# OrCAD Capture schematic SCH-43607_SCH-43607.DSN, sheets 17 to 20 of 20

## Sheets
17 P18_CPU MISC. &UART: size C
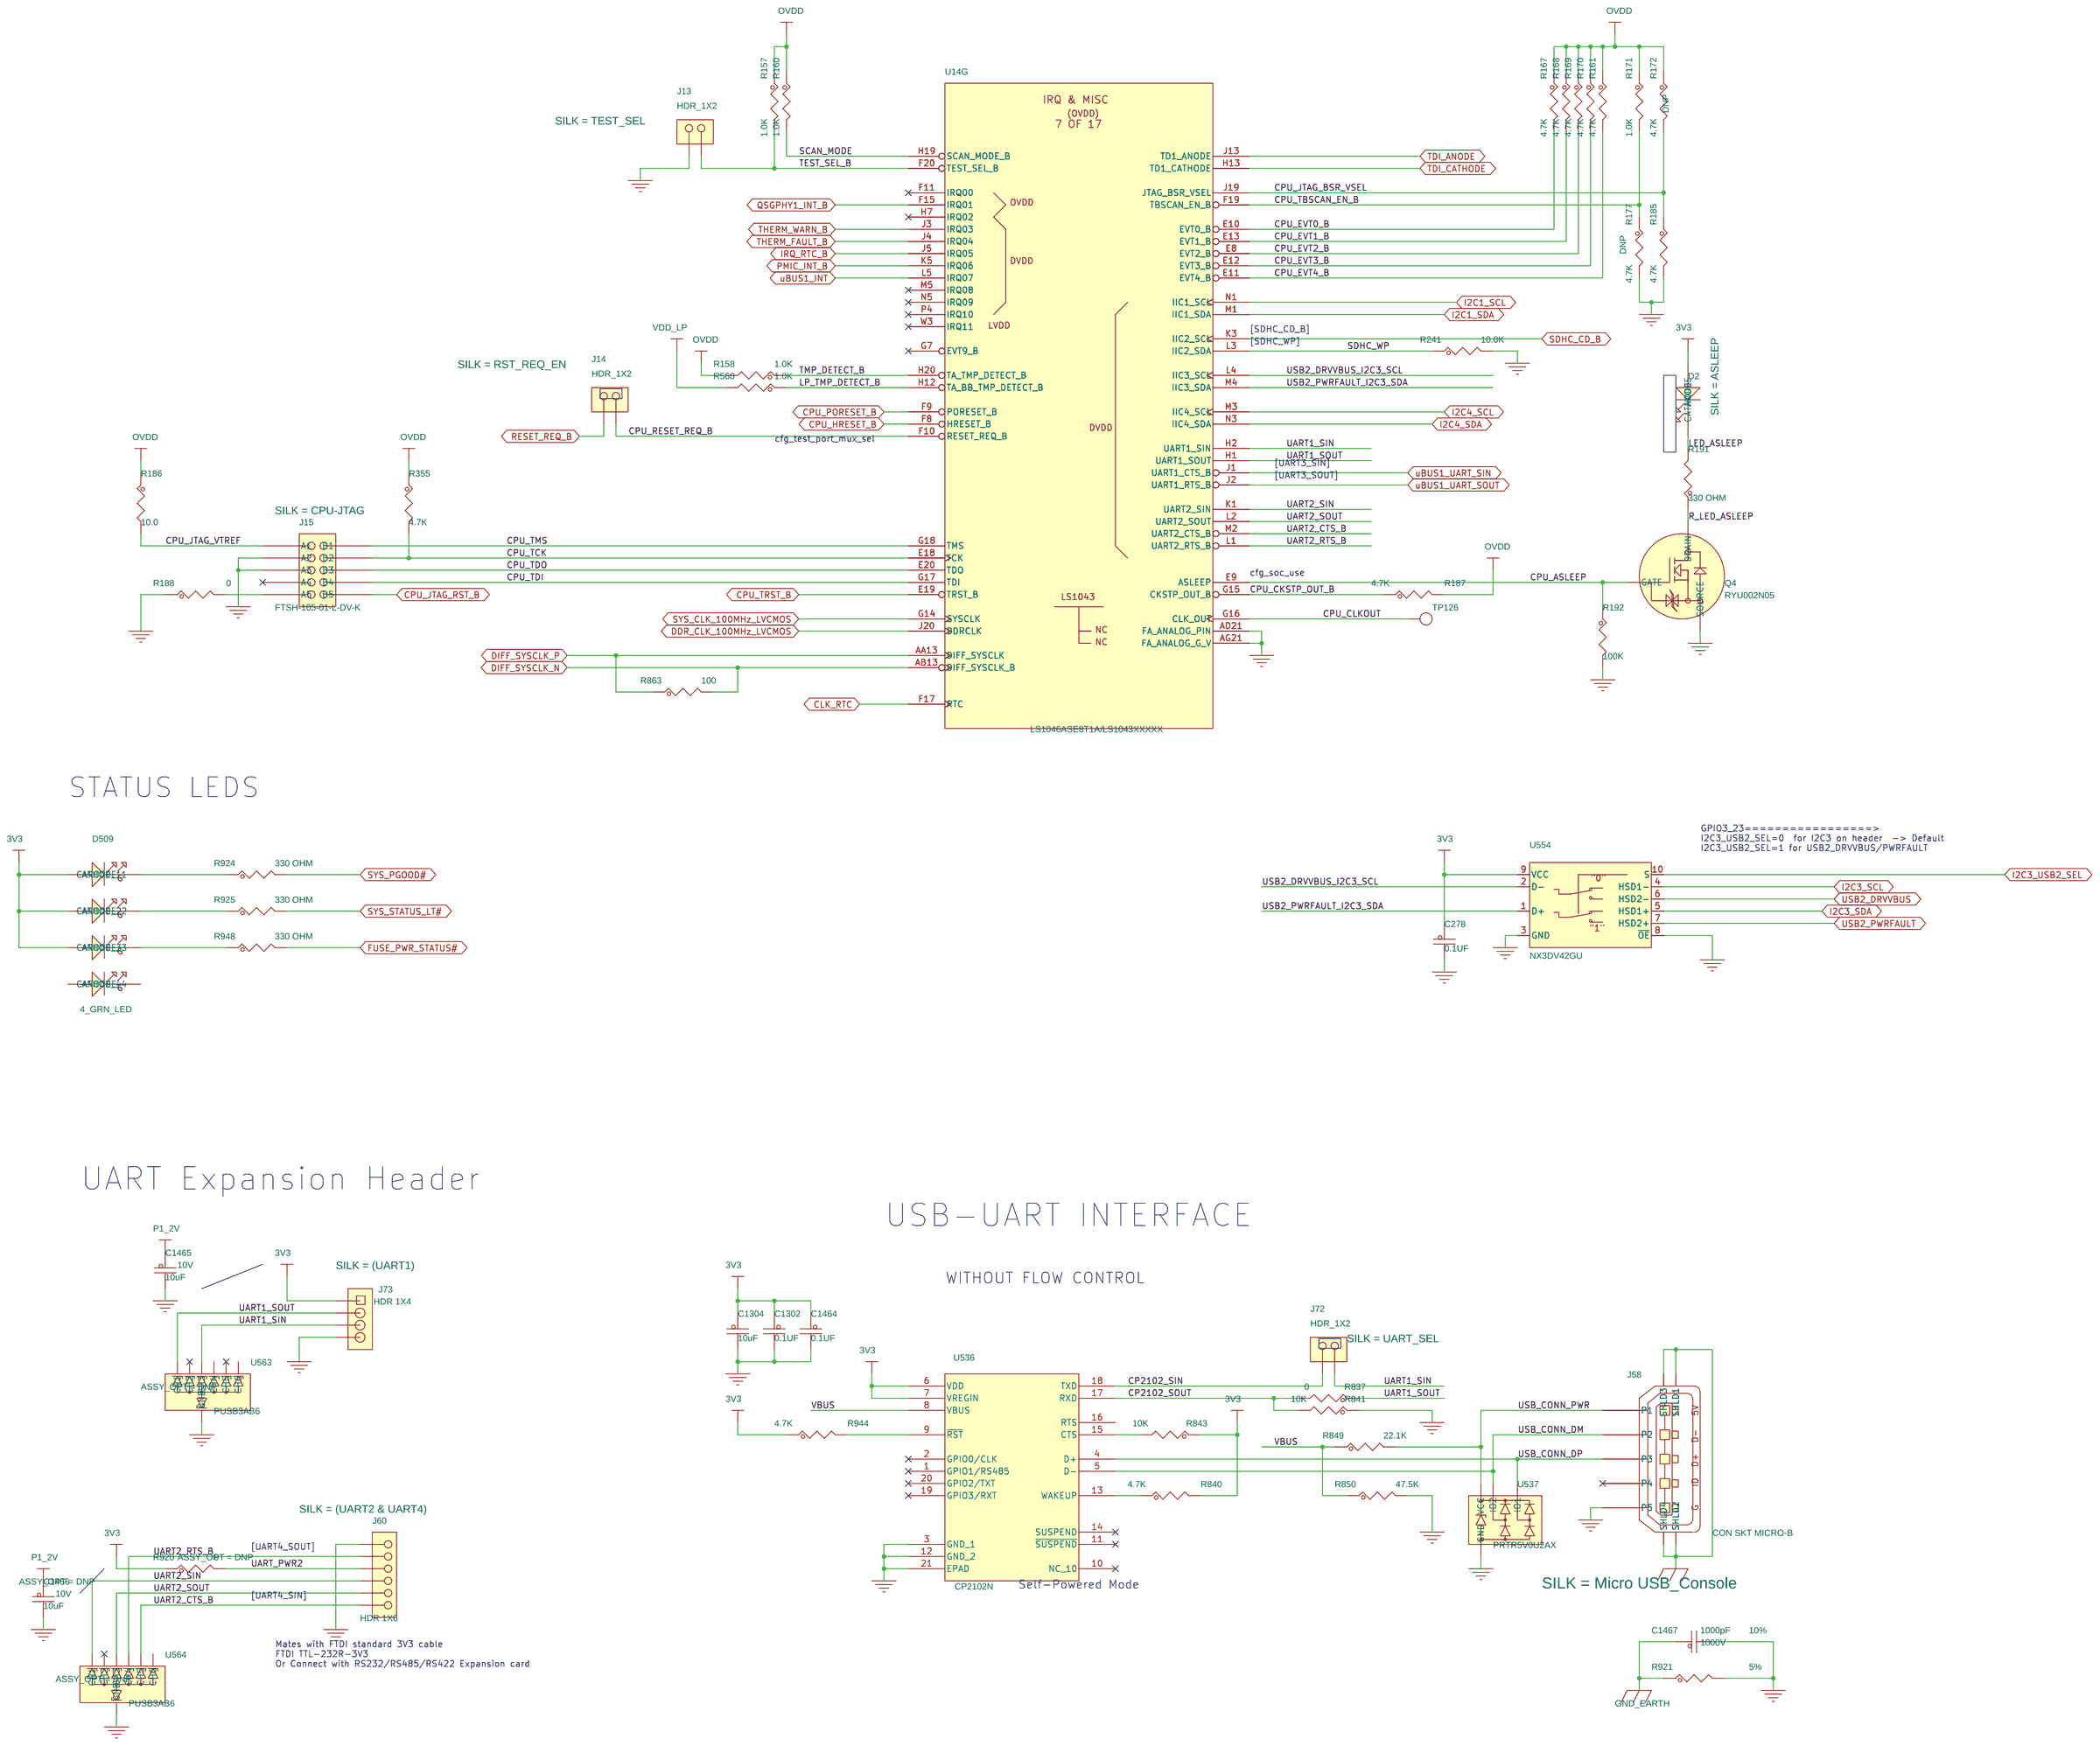
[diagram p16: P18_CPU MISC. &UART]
18 P19_CPU_RESET and GPIOs: size C
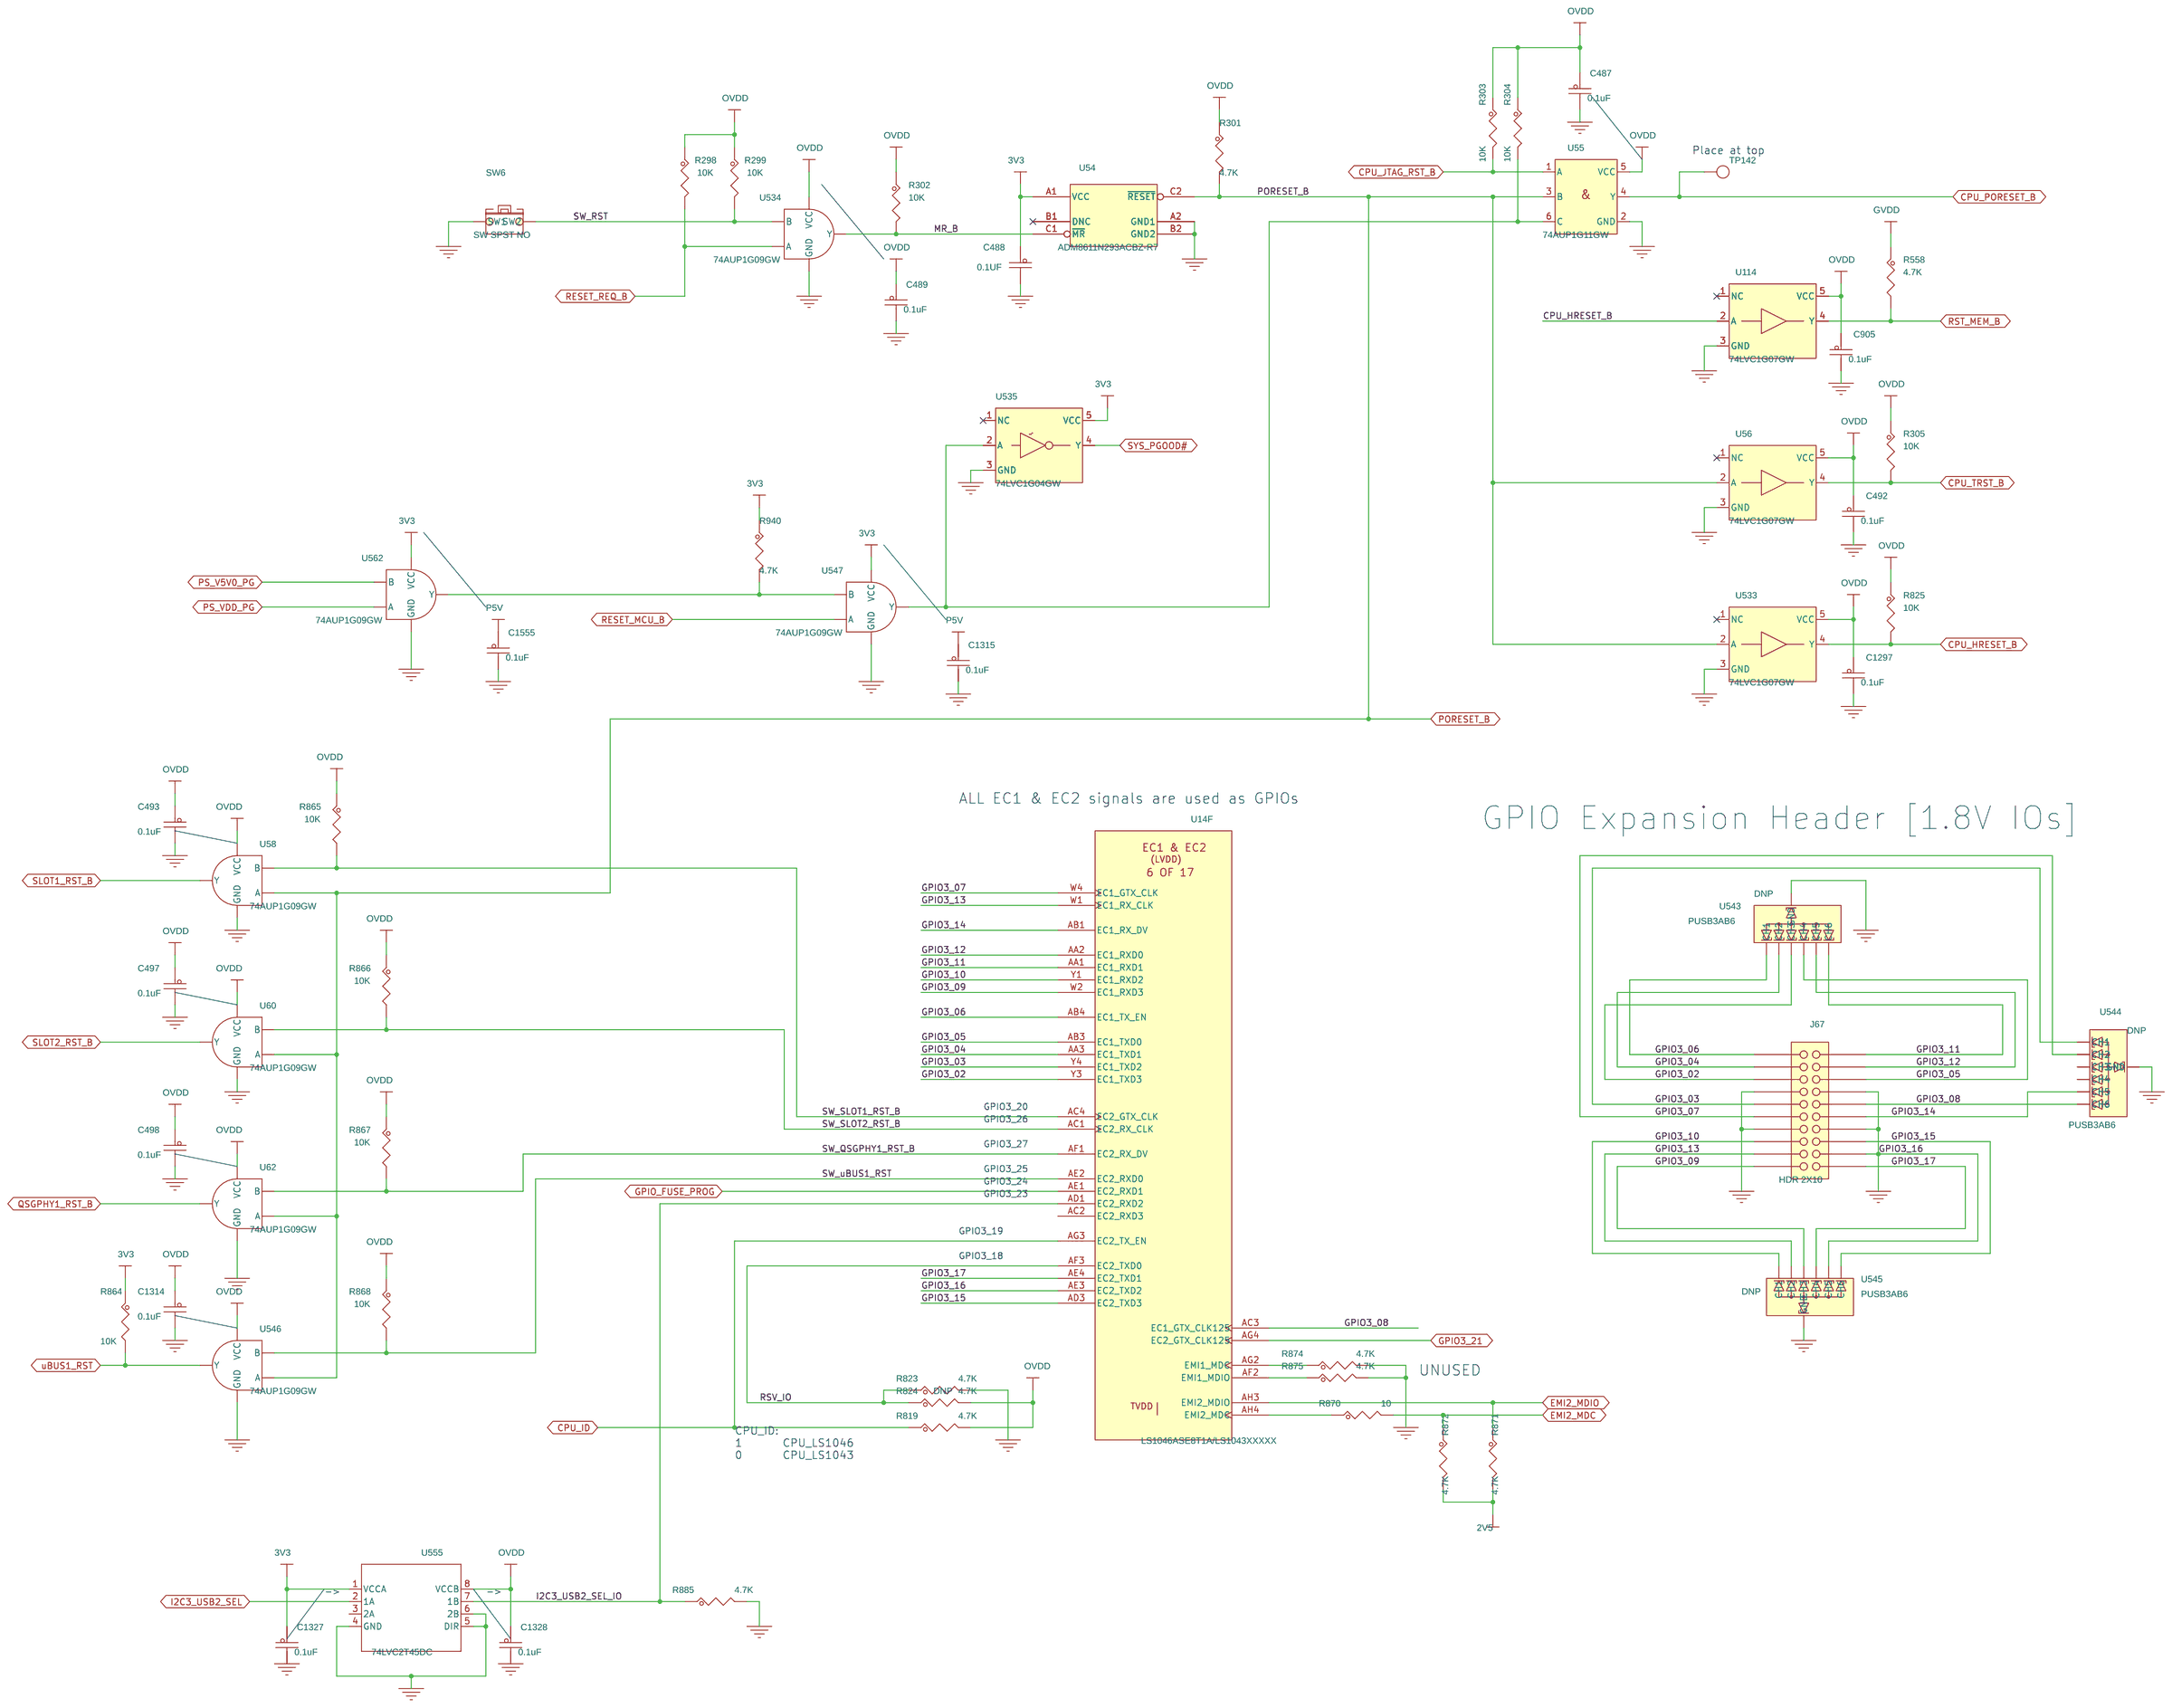
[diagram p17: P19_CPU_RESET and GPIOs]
19 P20_SD_SPI_MIKRO_CLICK: size C
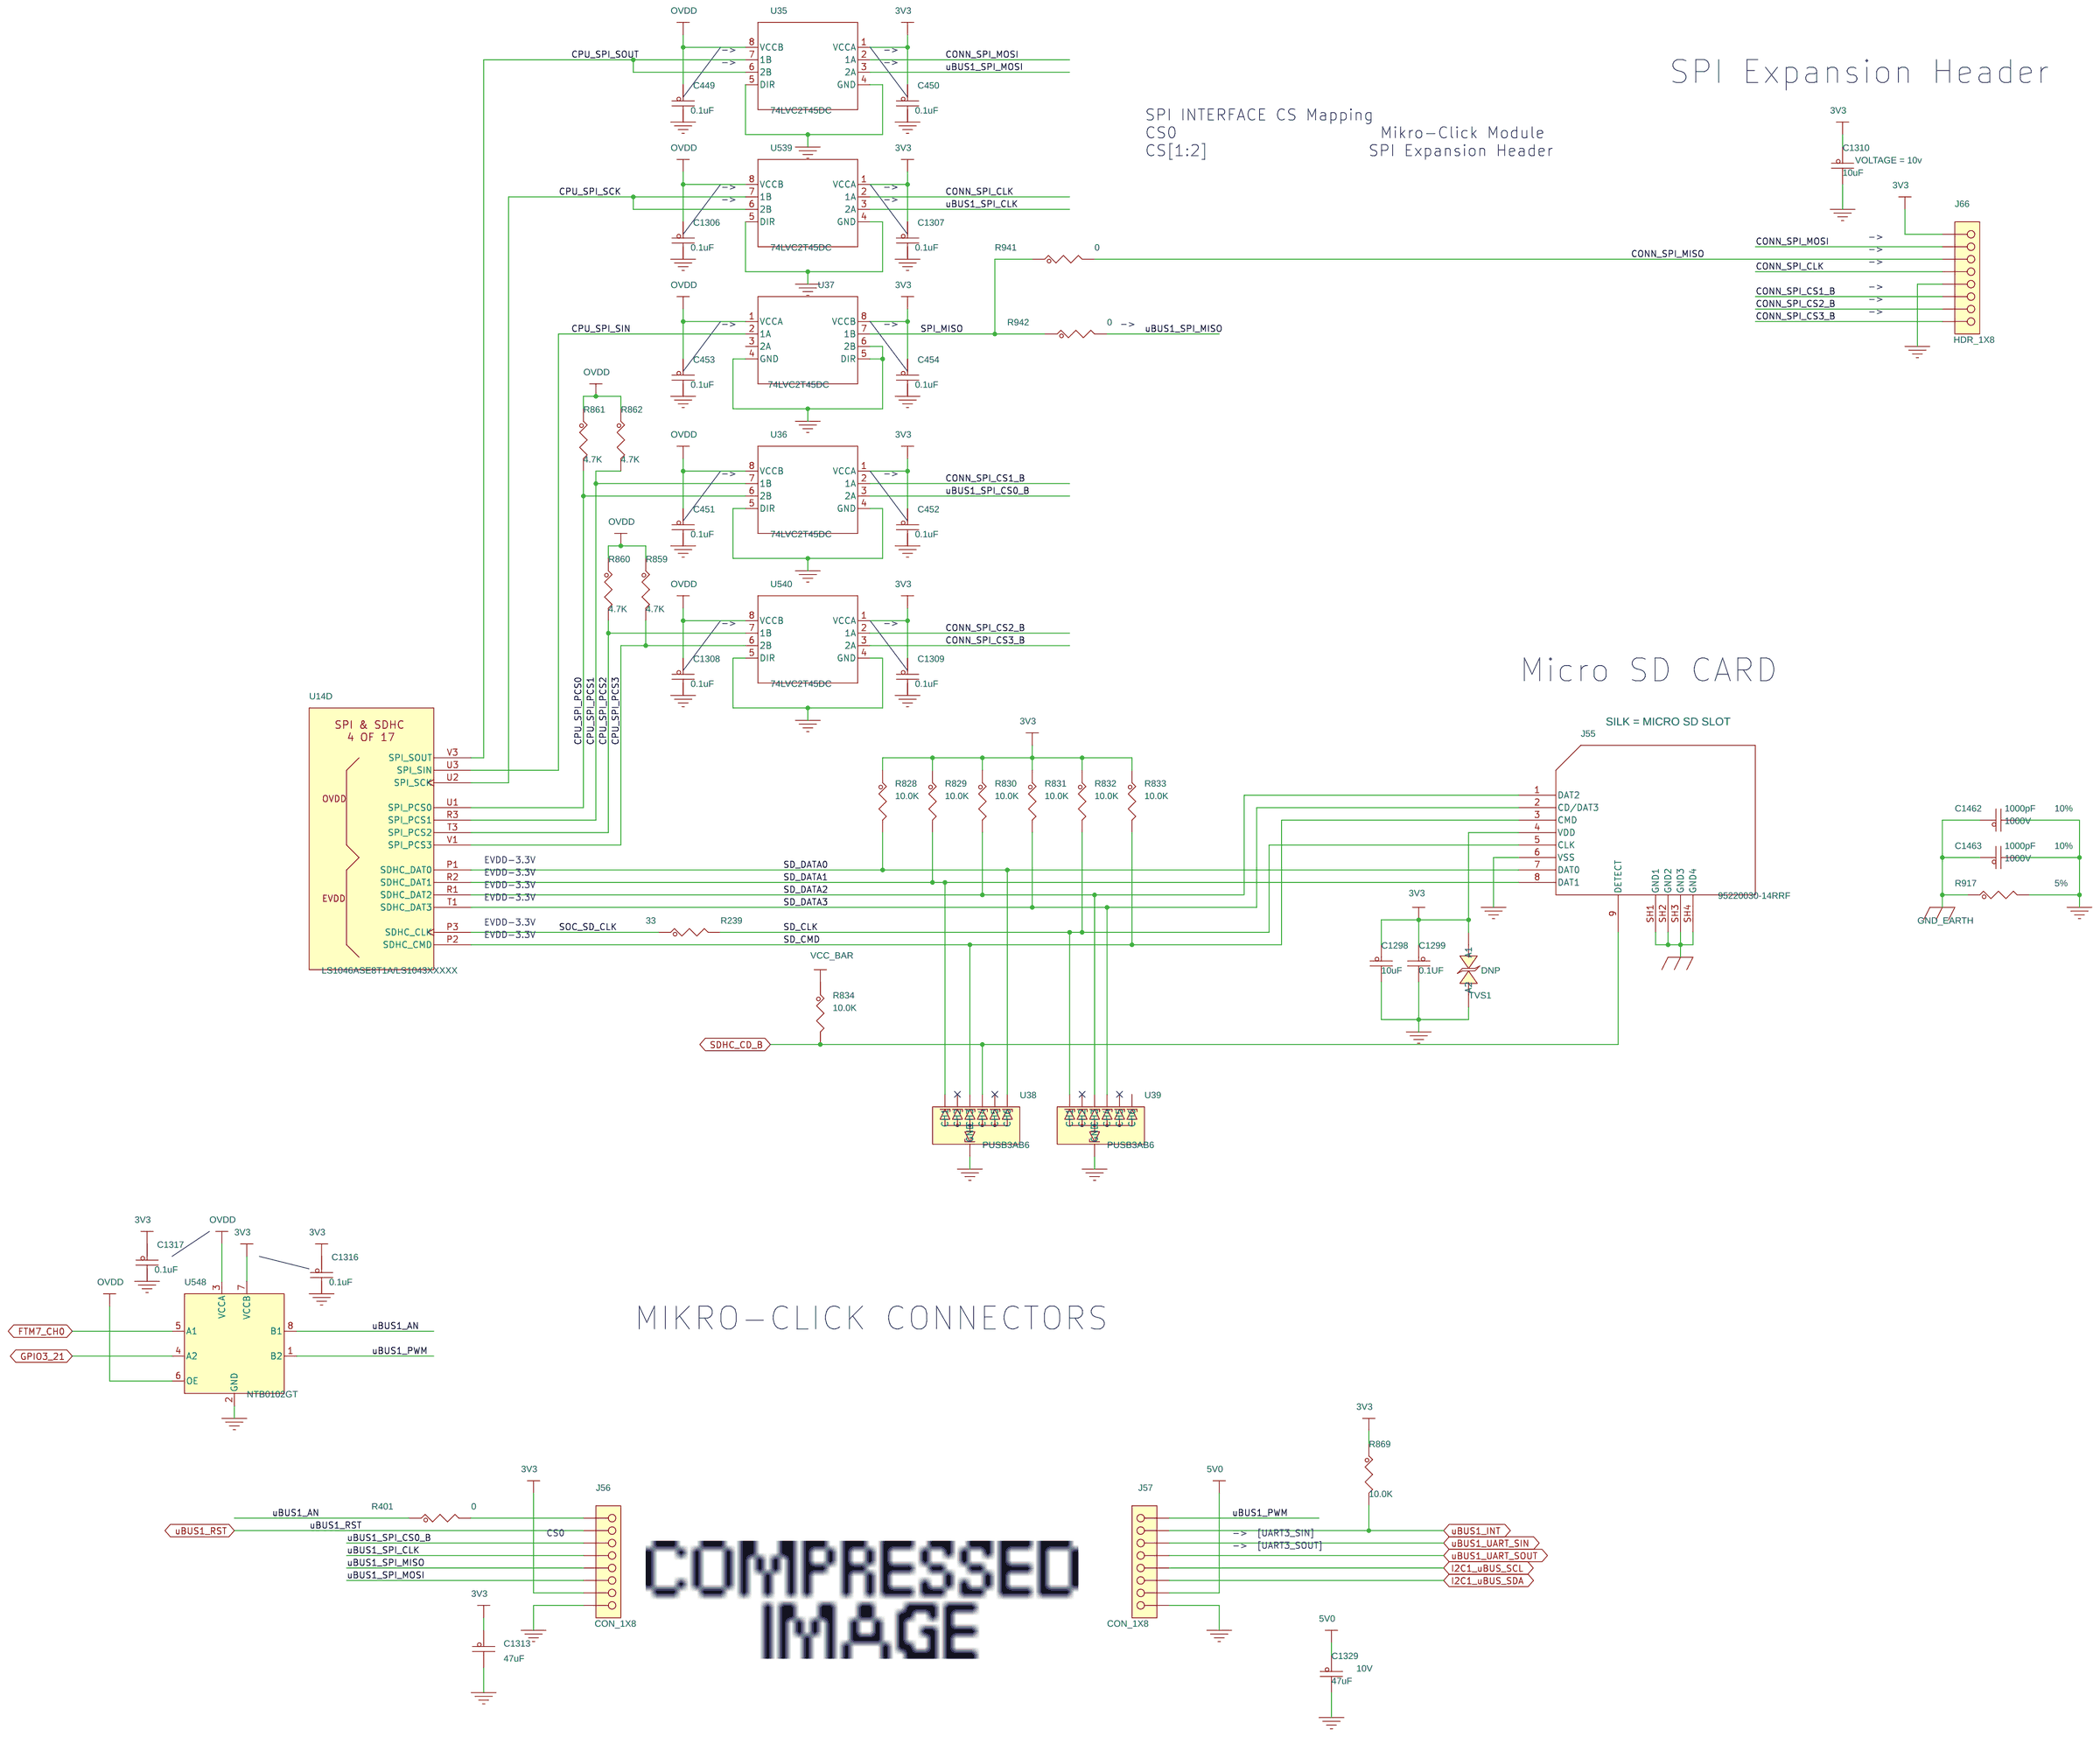
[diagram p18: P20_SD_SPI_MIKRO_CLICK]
20 P17_CPU USB[1:3]: size C
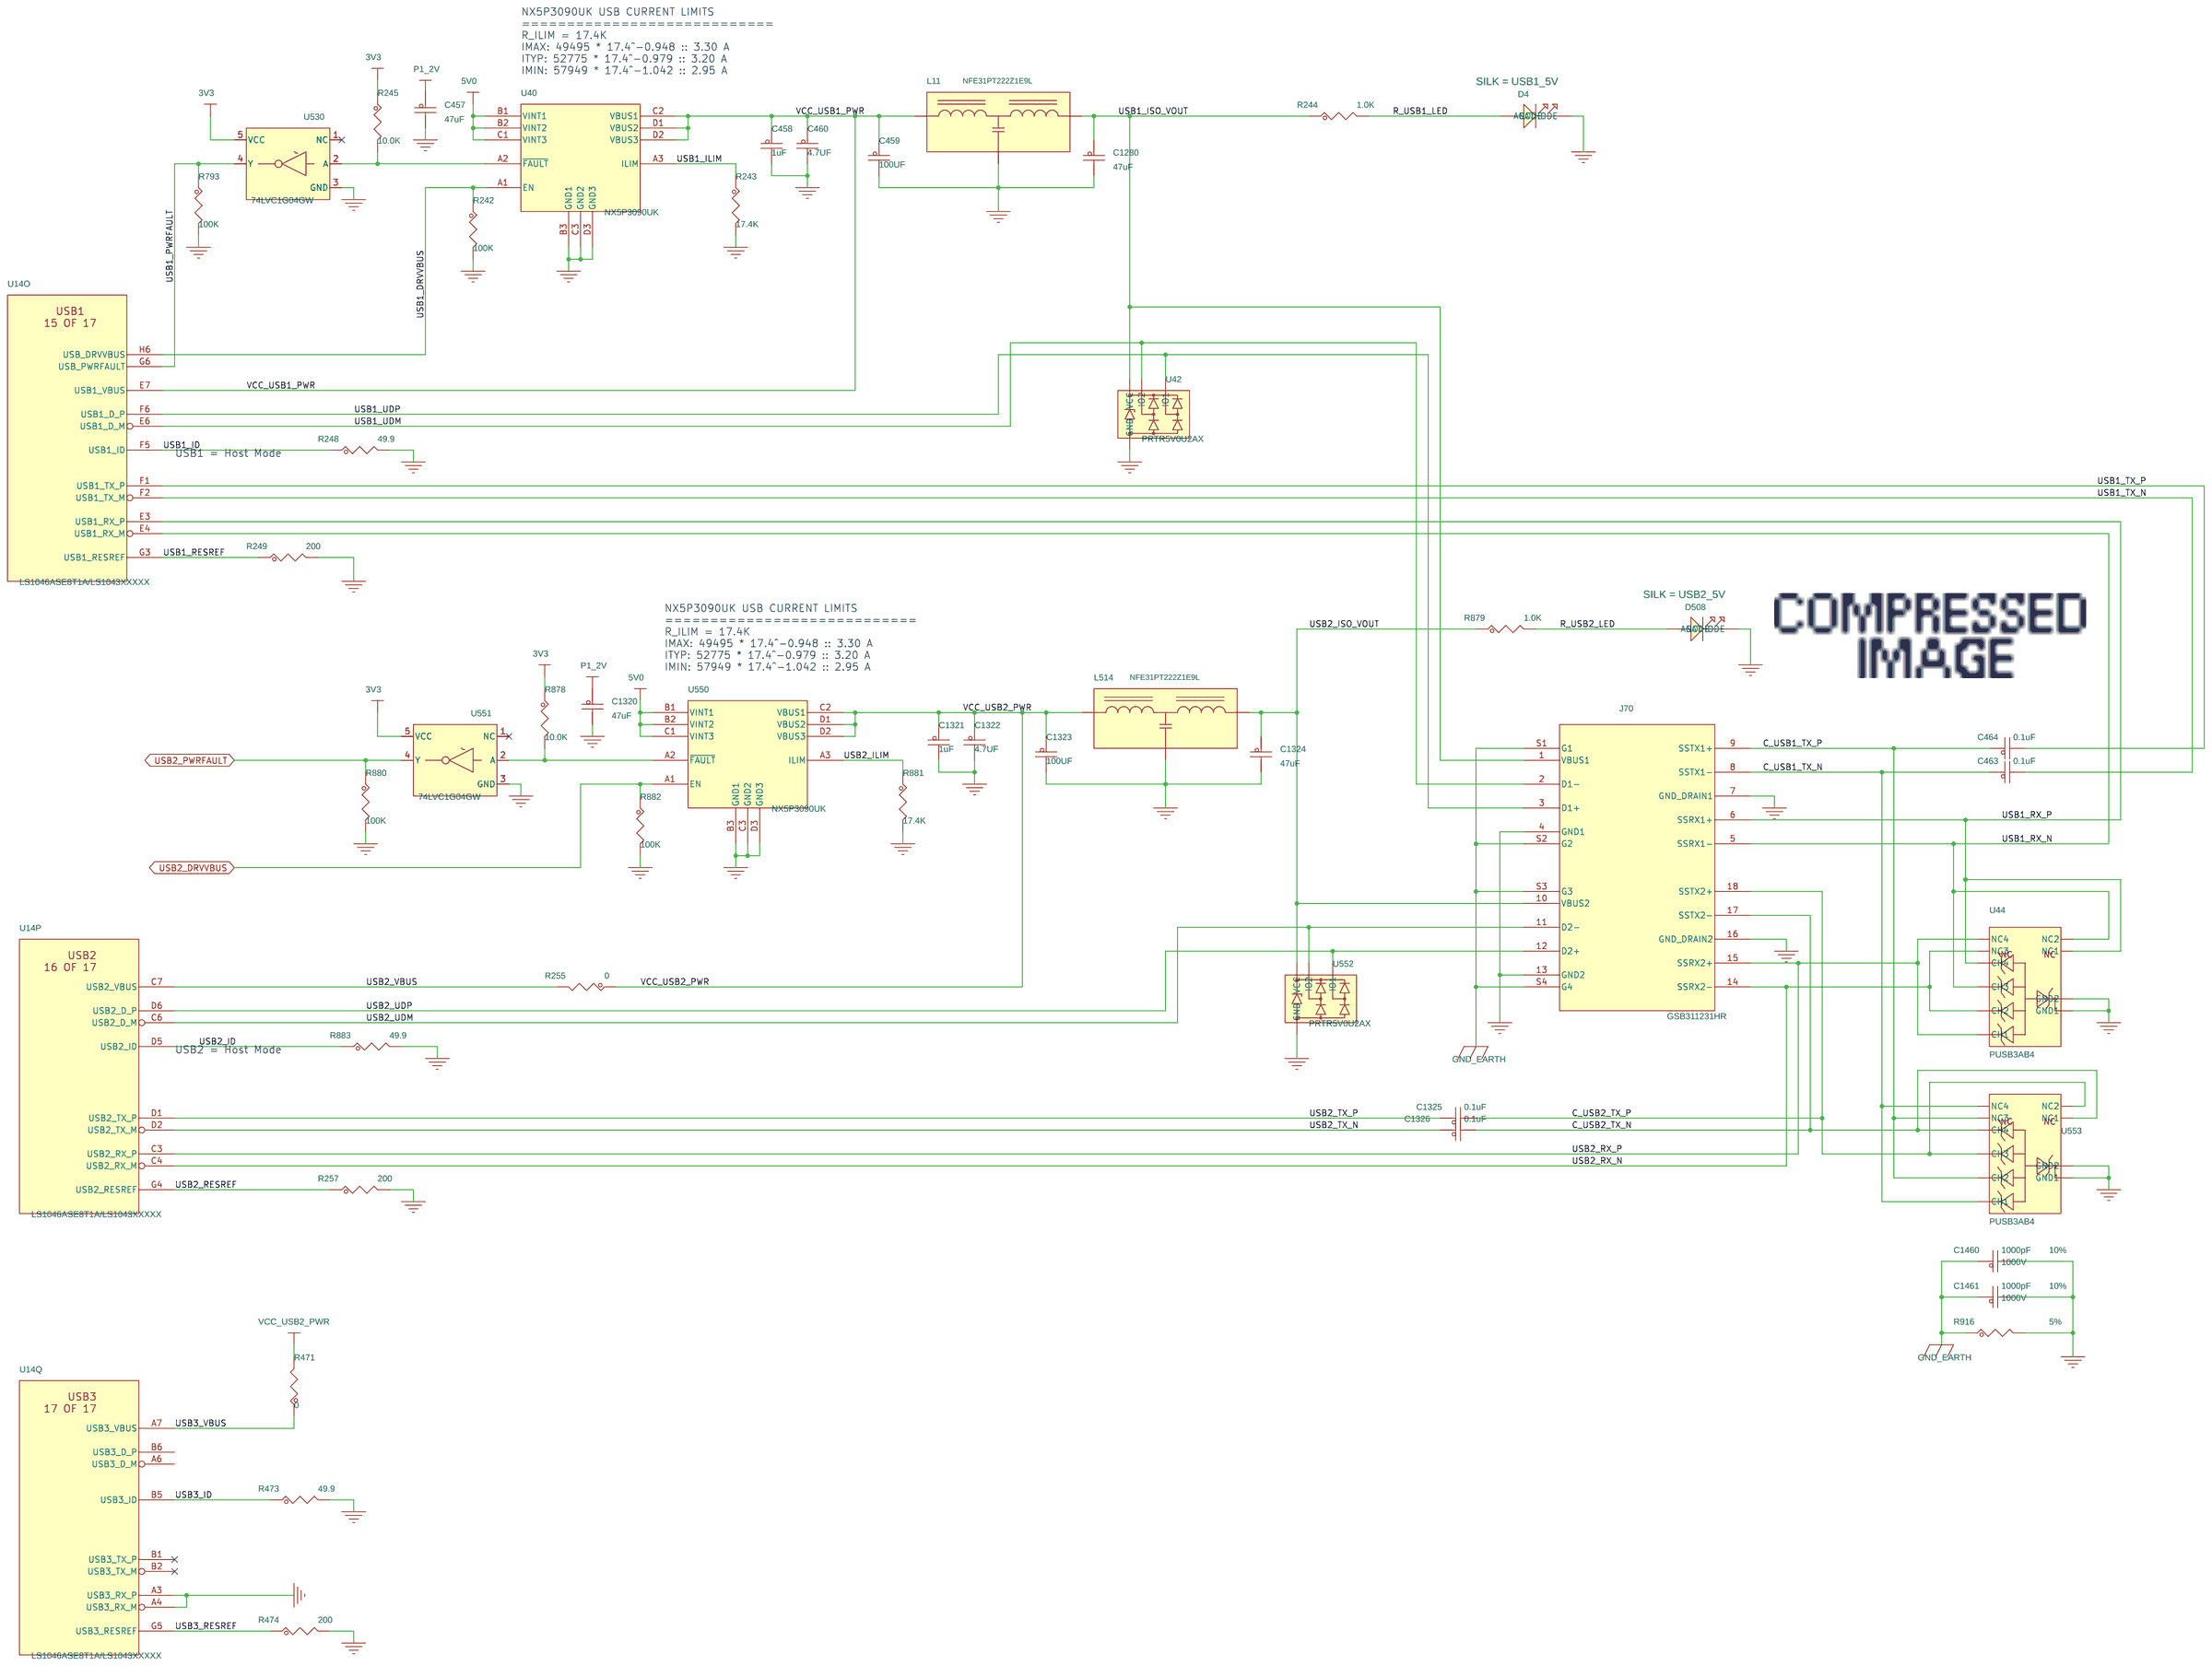
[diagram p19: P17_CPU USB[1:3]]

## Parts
sheet P17_CPU USB[1:3]
C457  47uF  [CC0805_OV]
C458  1uF  [CC0402_25]
C459  100UF  [CC1206_OV]
C460  4.7UF  [CC0402_25]
C463  0.1uF  [CC0201]
C464  0.1uF  [CC0201]
C1280  47uF  [CC0805_OV]
C1320  47uF  [CC0805_OV]
C1321  1uF  [CC0402_25]
C1322  4.7UF  [CC0402_25]
C1323  100UF  [CC1206_OV]
C1324  47uF  [CC0805_OV]
C1325  0.1uF  [CC0201]
C1326  0.1uF  [CC0201]
C1460  1000pF  [CC0805_OV]
C1461  1000pF  [CC0805_OV]
D4  LED_GREEN  [LED_0603]
D508  LED_GREEN  [LED_0603]
J70  GSB311231HR  [con_18p_usb3_ra_th]
L11  NFE31PT222Z1E9L  [IND_NFE31P]
L514  NFE31PT222Z1E9L  [IND_NFE31P]
R242  100K  [RC0402_25]
R243  17.4K  [RC0402_25]
R244  1.0K  [RC0402_25]
R245  10.0K  [RC0402_25]
R248  49.9  [RC0402_25]
R249  200  [RC0402_25]
R255  0  [RC0402_25]
R257  200  [RC0402_25]
R471  0  [RC0402_25]
R473  49.9  [RC0402_25]
R474  200  [RC0402_25]
R793  100K  [RC0402_25]
R878  10.0K  [RC0402_25]
R879  1.0K  [RC0402_25]
R880  100K  [RC0402_25]
R881  17.4K  [RC0402_25]
R882  100K  [RC0402_25]
R883  49.9  [RC0402_25]
R916  1.0M  [RC1206_OV]
U40  NX5P3090UK  [wlcsp12_0p4_1p38x1p68mm_smdp]
U42  PRTR5V0U2AX  [SOT143B]
U44  PUSB3AB4  [xson10_0p5_1p1x2p6mm]
U530  74LVC1G04GW  [sc70-5]
U550  NX5P3090UK  [wlcsp12_0p4_1p38x1p68mm_smdp]
U551  74LVC1G04GW  [sc70-5]
U552  PRTR5V0U2AX  [SOT143B]
U553  PUSB3AB4  [xson10_0p5_1p1x2p6mm]
sheet P18_CPU MISC. &UART
C278  0.1UF  [CC0402_25]
C1302  0.1UF  [CC0402_25]
C1304  10uF  [CC0603_OV]
C1464  0.1UF  [CC0402_25]
C1465  10uF  [CC0603_OV]
C1466  10uF  [CC0603_OV]
C1467  1000pF  [CC0805_OV]
D2  LED_YELLOW  [LED_0603]
D509  4_GRN_LED  [led_quad_2p54_th]
J13  HDR_1X2  [hdr1x2_50mil]
J14  HDR_1X2  [hdr1x2_50mil]
J15  FTSH-105-01-L-DV-K  [hdr205_10m_50_sm_k]
J58  CON SKT MICRO-B  [con_usb_5f_0p65_sm_ra_b]
J60  HDR 1X6  [hdr106_th_tsw]
J72  HDR_1X2  [hdr1x2_50mil]
J73  HDR 1X4  [JUMP1X4-6040]
Q4  RYU002N05  [SOT323_3]
R157  1.0K  [RC0402_25]
R158  1.0K  [RC0402_25]
R160  1.0K  [RC0402_25]
R161  4.7K  [RC0402_25]
R167  4.7K  [RC0402_25]
R168  4.7K  [RC0402_25]
R169  4.7K  [RC0402_25]
R170  4.7K  [RC0402_25]
R171  1.0K  [RC0402_25]
R172  4.7K  [RC0402_25]
R177  4.7K  [RC0402_25]
R185  4.7K  [RC0402_25]
R186  10.0  [RC0402_25]
R187  4.7K  [RC0402_25]
R188  0  [RC0402_25]
R191  330 OHM  [RC0402_25]
R192  100K  [RC0402_25]
R241  10.0K  [RC0402_25]
R355  4.7K  [RC0402_25]
R560  1.0K  [RC0402_25]
R837  0  [RC0402_25]
R840  4.7K  [RC0402_25]
R841  10K  [RC0402_25]
R843  10K  [RC0402_25]
R849  22.1K  [RC0402_25]
R850  47.5K  [RC0402_25]
R863  100  [RC0201]
R920  0  [RC0402_25]
R921  1.0M  [RC1206_OV]
R924  330 OHM  [RC0402_25]
R925  330 OHM  [RC0402_25]
R944  4.7K  [RC0402_25]
R948  330 OHM  [RC0402_25]
TP126  TPAD_020  [tpad_020]
U536  CP2102N  [qfn20_3x3mm_b]
U537  PRTR5V0U2AX  [SOT143B]
U554  NX3DV42GU  [uqfn10_0p4_1p45x1p85]
U563  PUSB3AB6  [xson7_0p5_2p2x1p2]
U564  PUSB3AB6  [xson7_0p5_2p2x1p2]
sheet P19_CPU_RESET and GPIOs
C487  0.1uF  [CC0201]
C488  0.1UF  [CC0402_25]
C489  0.1uF  [CC0201]
C492  0.1uF  [CC0201]
C493  0.1uF  [CC0201]
C497  0.1uF  [CC0201]
C498  0.1uF  [CC0201]
C905  0.1uF  [CC0201]
C1297  0.1uF  [CC0201]
C1314  0.1uF  [CC0201]
C1315  0.1uF  [CC0201]
C1327  0.1uF  [CC0201]
C1328  0.1uF  [CC0201]
C1555  0.1uF  [CC0201]
J67  HDR 2X10  [CON_TSM_20M_2P54_SM]
R298  10K  [RC0402_25]
R299  10K  [RC0402_25]
R301  4.7K  [RC0402_25]
R302  10K  [RC0402_25]
R303  10K  [RC0402_25]
R304  10K  [RC0402_25]
R305  10K  [RC0402_25]
R558  4.7K  [RC0402_25]
R819  4.7K  [RC0402_25]
R823  4.7K  [RC0402_25]
R824  4.7K  [RC0402_25]
R825  10K  [RC0402_25]
R864  10K  [RC0402_25]
R865  10K  [RC0402_25]
R866  10K  [RC0402_25]
R867  10K  [RC0402_25]
R868  10K  [RC0402_25]
R870  10  [RC0402_25]
R871  4.7K  [RC0402_25]
R872  4.7K  [RC0402_25]
R874  4.7K  [RC0402_25]
R875  4.7K  [RC0402_25]
R885  4.7K  [RC0402_25]
R940  4.7K  [RC0402_25]
SW6  SW SPST NO  [sw2_4p45_4x3_sm]
TP142  TPAD_020  [tpad_020]
U54  ADM8611N293ACBZ-R7  [wlcsp6_0p5_0p98x1p48]
U55  74AUP1G11GW  [sot-363_0p65_smt]
U56  74LVC1G07GW  [sc70-5]
U58  74AUP1G09GW  [SC70-5]
U60  74AUP1G09GW  [SC70-5]
U62  74AUP1G09GW  [SC70-5]
U114  74LVC1G07GW  [sc70-5]
U533  74LVC1G07GW  [sc70-5]
U534  74AUP1G09GW  [SC70-5]
U535  74LVC1G04GW  [sc70-5]
U543  PUSB3AB6  [xson7_0p5_2p2x1p2]
U544  PUSB3AB6  [xson7_0p5_2p2x1p2]
U545  PUSB3AB6  [xson7_0p5_2p2x1p2]
U546  74AUP1G09GW  [SC70-5]
U547  74AUP1G09GW  [SC70-5]
U555  74LVC2T45DC  [SSOP8_DCU]
U562  74AUP1G09GW  [SC70-5]
sheet P20_SD_SPI_MIKRO_CLICK
C449  0.1uF  [CC0201]
C450  0.1uF  [CC0201]
C451  0.1uF  [CC0201]
C452  0.1uF  [CC0201]
C453  0.1uF  [CC0201]
C454  0.1uF  [CC0201]
C1298  10uF  [CC0603_OV]
C1299  0.1UF  [CC0402_25]
C1306  0.1uF  [CC0201]
C1307  0.1uF  [CC0201]
C1308  0.1uF  [CC0201]
C1309  0.1uF  [CC0201]
C1310  10uF  [CC0603_OV]
C1313  47uF  [CC0805_OV]
C1316  0.1uF  [CC0201]
C1317  0.1uF  [CC0201]
C1329  47uF  [CC0805_OV]
C1462  1000pF  [CC0805_OV]
C1463  1000pF  [CC0805_OV]
J55  95220030-14RRF  [CON_SDCARD_95220]
J56  CON_1X8  [con_1x8_skt_2p54_th]
J57  CON_1X8  [con_1x8_skt_2p54_th]
J66  HDR_1X8  [JUMP1X8-6040]
R239  33  [RC0402_25]
R401  0  [RC0402_25]
R828  10.0K  [RC0402_25]
R829  10.0K  [RC0402_25]
R830  10.0K  [RC0402_25]
R831  10.0K  [RC0402_25]
R832  10.0K  [RC0402_25]
R833  10.0K  [RC0402_25]
R834  10.0K  [RC0402_25]
R859  4.7K  [RC0402_25]
R860  4.7K  [RC0402_25]
R861  4.7K  [RC0402_25]
R862  4.7K  [RC0402_25]
R869  10.0K  [RC0402_25]
R917  1.0M  [RC1206_OV]
R941  0  [RC0402_25]
R942  0  [RC0402_25]
TVS1  SESD0402X1BN  [diode_bidir_0402]
U14  LS1046ASE8T1A/LS1043XXXXX  [BGA780_0P8_23X23MM]  (sections A,B,C,D,E,F,G,H,I,J,K,L,M,N,O,P,Q)
U35  74LVC2T45DC  [SSOP8_DCU]
U36  74LVC2T45DC  [SSOP8_DCU]
U37  74LVC2T45DC  [SSOP8_DCU]
U38  PUSB3AB6  [xson7_0p5_2p2x1p2]
U39  PUSB3AB6  [xson7_0p5_2p2x1p2]
U539  74LVC2T45DC  [SSOP8_DCU]
U540  74LVC2T45DC  [SSOP8_DCU]
U548  NTB0102GT  [xson_8p]

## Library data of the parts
C457 C1280 C1313 C1320 C1324 C1329 = CAP_NP: CAP CER 47uF 10V 20% X5R 0805; AGILE_PN: 150-78979; CAD_APPROVED: Yes; FPLIST: CC0805_OV,CC0805,0805_CC; HEIGHT: 1.45 MM; MFG_NAME01: TDK; MFG_PN01: C2012X5R1A476M125AC; ROHS: Yes; Tolerance: 20%; VOLTAGE: 10V
C458 C1321 = CAP_NP: CAP CER 1uF 25V 10% X5R 0402; AGILE_PN: 150-80001; CAD_APPROVED: Yes; FPLIST: CC0402_25,CC0402_HD,0402_CC; HEIGHT: 0.55MM; MFG_NAME01: MURATA; MFG_PN01: GRM155R61E105KA12; PRIORITY_PN: 021-00242; ROHS: Yes; ROOM: USB2; Temp_Range: -55°C to +85°C; Tolerance: 10%; VOLTAGE: 25 V
C459 C1323 = CAP_NP: CAP CER 100UF 6.3V 20% X5R 1206; AGILE_PN: 150-77574; CAD_APPROVED: Yes; FPLIST: CC1206_OV,CC1206,1206_CC; HEIGHT: 1.9 MM; MFG_NAME01: Murata; MFG_PN01: GRM31CR60J107ME39L; ROHS: Yes; Tolerance: 20%; VOLTAGE: 6.3V
C460 C1322 = CAP_NP: CAP CER 4.7UF 10V 20% X5R 0402; AGILE_PN: 150-79667; CAD_APPROVED: Yes; FPLIST: CC0402_25,CC0402_HD,0402_CC; HEIGHT: 0.65MM; MFG_NAME01: Murata; MFG_PN01: GRM155R61A475MEAA; PRIORITY_PN: 921-00228; ROHS: Yes; ROOM: VTT_VREF_PS; Temp_Range: -55 to 85; Tolerance: 20%; VOLTAGE: 10V
C449-C454 C463 C464 C487 C489 C492 C493 C497 C498 C905 C1297 C1306-C1309 C1314-C1317 C1325-C1328 C1555 = CAP_NP: CAP CER 0.1uF 16V 10% X5R 0201; AGILE_PN: 150-80059; CAD_APPROVED: Yes; FPLIST: CC0201,CC0201_HD,0201_CC; HEIGHT: 0.33MM; MFG_NAME01: MURATA; MFG_PN01: GRM033R61C104KE14D; ROHS: Yes; Temp_Range: -55 to +85°C; Tolerance: 10%; VOLTAGE: 16V
C1460-C1463 C1467 = CAP_NP: CAP CER 1000pF 1000V 10% X7R 0805; AGILE_PN: 150-78841; CAD_APPROVED: Yes; FPLIST: CC0805_OV,CC0805,0805_CC; HEIGHT: 1.4MM; MFG_NAME01: Kemet; MFG_PN01: C0805C102KDRACTU; ROHS: Yes; Tolerance: 10%; VOLTAGE: 1000V
D4 = LED: LED ULTRA-BRIGHT GREEN SMT 0603; AGILE_PN: 370-75077; CAD_APPROVED: YES; HEIGHT: 0.8MM; MFG_NAME01: LITE ON; MFG_PN01: LTST-C190KGKT; ROHS: Yes; SILK: USB1_5V
D508 = LED: LED ULTRA-BRIGHT GREEN SMT 0603; AGILE_PN: 370-75077; CAD_APPROVED: YES; HEIGHT: 0.8MM; MFG_NAME01: LITE ON; MFG_PN01: LTST-C190KGKT; ROHS: Yes; SILK: USB2_5V
J70 = GSB311231HR_USB18P: CON 18 USB 3.0 SKT RA TH TYPE A 2MM SP 618H AU 94L; AGILE_PN: 210-80509; CAD_APPROVED: Yes; HEIGHT: 15.7MM; MFG_NAME01: Amphenol; ROHS: Yes
L11 L514 = NFE31P: FILTER LC 2200PF 6A 25V 1206; AGILE_PN: 180-75042; CAD_APPROVED: Yes; FPLIST: IND_NFE31P,NFM60R; HEIGHT: 1.75MM; MFG_NAME01: MURATA; PART_TYPE: FERRITE; ROHS: Yes; TOL: 50%; Tolerance: 50%
R192 R242 R793 R880 R882 = RES: RES MF 100K 1/16W 1% 0402; AGILE_PN: 470-76240; CAD_APPROVED: Yes; FPLIST: RC0402_25,RC0402_HD,0402_CC; HEIGHT: 0.4MM; MFG_NAME01: NIC COMPONENTS CORP; MFG_PN01: NRCL04F1003TRF; ROHS: Yes; Tolerance: 1%
R243 R881 = RES: RES MF 17.4K 1/10W 1% AEC-Q200 0402; AGILE_PN: 470-30972; CAD_APPROVED: Yes; FPLIST: RC0402_25,RC0402_HD,0402_CC; HEIGHT: 0.40 MM; MFG_NAME01: KOA SPEER; MFG_PN01: RK73H1ETTP1742F; ROHS: Yes; Temp_Range: -55C to +155C; Tolerance: 1%
R157 R158 R160 R171 R244 R560 R879 = RES: RES MF 1.0K 1/16W 1% 0402; AGILE_PN: 470-76037; CAD_APPROVED: Yes; FPLIST: RC0402_25,RC0402_HD,RC0402_X2,0402_CC; HEIGHT: 0.4MM; MFG_NAME01: YAGEO AMERICA; MFG_PN01: RC0402FR-071KL; ROHS: Yes; Tolerance: 1%
R241 R245 R828-R834 R869 R878 = RES: RES MF 10.0K 1/16W 1% 0402; AGILE_PN: 470-80574; CAD_APPROVED: Yes; FPLIST: RC0402_25,RC0402_HD,0402_CC; HEIGHT: 0.4MM; MFG_NAME01: WALSIN TECHNOLOGY CORP.; MFG_PN01: WR04X1002FTL; ROHS: Yes; Tolerance: 1%
R248 R473 R883 = RES: RES MF 49.9 OHM 1/16W 1% 0402; AGILE_PN: 470-75360; CAD_APPROVED: Yes; FPLIST: RC0402_25,RC0402_HD,0402_CC; HEIGHT: 0.4MM; MFG_NAME01: BOURNS; MFG_PN01: CR0402-FX-49R9GLF; ROHS: Yes; Tolerance: 1%
R249 R257 R474 = RES: RES MF 200 OHM 1/10W 1% 0402; AGILE_PN: 470-80287; CAD_APPROVED: Yes; FPLIST: RC0402_25,RC0402_HD,0402_CC; HEIGHT: 0.4 MM; MFG_NAME01: Panasonic; MFG_PN01: ERJ2RKF2000X; ROHS: Yes; Tolerance: 1%
R188 R255 R401 R471 R837 R941 R942 = RES: RES MF ZERO OHM 1/10W -- 0402; AGILE_PN: 470-79965; CAD_APPROVED: Yes; FPLIST: RC0402_25,RC0402_HD,RC0402_X2,0402_CC; HEIGHT: 0.4MM; MFG_NAME01: Panasonic; MFG_PN01: ERJ-2GE0R00X; ROHS: Yes
R916 R917 R921 = RES: RES MF 1.0M 1/4W 5% 1206; AGILE_PN: 470-75658; CAD_APPROVED: Yes; FPLIST: RC1206_OV,RC1206,1206_CC; HEIGHT: 0.75MM; MFG_NAME01: BOURNS; MFG_PN01: CR1206JW105ELF; ROHS: Yes; Tolerance: 5%
U40 U550 = NX5P3090UK_WLCSP12: IC USB PD TYPE C CURRENT LIMITED PWR SW 2.5-5.5V WLCSP12; AGILE_PN: 312-81574; CAD_APPROVED: Yes; HEIGHT: 0.565 MM; MFG_NAME01: NXP SEMICONDUCTORS; MFG_PN01: NX5P3090UK,012; ROHS: Yes
U42 U537 U552 = PRTR5V0U2AX: DIODE ARRAY ESD PROTECTION 5.5V AEC-Q101 SOT 143B; AGILE_PN: 480-78929; CAD_APPROVED: Yes; HEIGHT: 1.1MM; MFG_NAME01: NEXPERIA; MFG_PN01: PRTR5V0U2AX,215; ROHS: Yes; ROOM: USB1
U44 U553 = DIODE_ESD_4CH_PUSB3AB4: DIODE ARRAY ESD 3.3V 7A DFN2510A-10; AGILE_PN: 480-78994; CAD_APPROVED: Yes; HEIGHT: 0.5MM; MFG_NAME01: NEXPERIA; MFG_PN01: PUSB3AB4Z; ROHS: Yes
U530 U535 U551 = NC7SZ14: IC INV SGL 1.65-5.5V TSSOP5; AGILE_PN: 315-81077; CAD_APPROVED: Yes; HEIGHT: 1.1MM; MFG_NAME01: NEXPERIA; MFG_PN01: 74LVC1G04GW,125; ROHS: Yes
C278 = CAP_NP: CAP CER 0.1UF 25V 10% X5R 0402; AGILE_PN: 150-80045; CAD_APPROVED: Yes; FPLIST: CC0402_25,CC0402_HD,0402_CC; HEIGHT: 0.55MM; MFG_NAME01: Samsung Electro Mechanics; MFG_PN01: CL05A104KA5NNNC; PRIORITY_PN: 021-00389; ROHS: Yes; ROOM: LED; Tolerance: 10%; VOLTAGE: 25V
C488 C1299 C1302 C1464 = CAP_NP: CAP CER 0.1UF 25V 10% X5R 0402; AGILE_PN: 150-80045; CAD_APPROVED: Yes; FPLIST: CC0402_25,CC0402_HD,0402_CC; HEIGHT: 0.55MM; MFG_NAME01: Samsung Electro Mechanics; MFG_PN01: CL05A104KA5NNNC; ROHS: Yes; TOL: 10%; Tolerance: 10%; VOLTAGE: 25V
C1298 C1304 C1310 = CAP_NP: CAP CER 10UF 10V 10% X5R 0603; AGILE_PN: 150-78675; CAD_APPROVED: Yes; FPLIST: CC0603_OV,CC0603,0603_CC; HEIGHT: 1.016MM; MFG_NAME01: MURATA; MFG_PN01: GRM188R61A106KE69D; ROHS: Yes; Temp_Range: -55°C ~ 85°C; Tolerance: 10%; VOLTAGE: 10v
C1465 = CAP_NP: CAP CER 10UF 10V 10% X5R 0603; AGILE_PN: 150-78675; CAD_APPROVED: Yes; FPLIST: CC0603_OV,CC0603,0603_CC; HEIGHT: 1.016MM; MFG_NAME01: MURATA; MFG_PN01: GRM188R61A106KE69D; PRIORITY_PN: 021-00358; ROHS: Yes; ROOM: SDHC; SIGNAL_MODEL: DEFAULT_CAPACITOR_1e+07pF_2_1; TOL: 10%; Temp_Range: -55°C ~ 85°C; Tolerance: 10%; VOLTAGE: 10V
C1466 = CAP_NP: CAP CER 10UF 10V 10% X5R 0603; AGILE_PN: 150-78675; ASSY_OPT: DNP; CAD_APPROVED: Yes; FPLIST: CC0603_OV,CC0603,0603_CC; HEIGHT: 1.016MM; MFG_NAME01: MURATA; MFG_PN01: GRM188R61A106KE69D; PRIORITY_PN: 021-00358; ROHS: Yes; ROOM: SDHC; SIGNAL_MODEL: DEFAULT_CAPACITOR_1e+07pF_2_1; TOL: 10%; Temp_Range: -55°C ~ 85°C; Tolerance: 10%; VOLTAGE: 10V
D2 = LED: LED ULTRA-BRIGHT YELLOW 30MA 5V SMT 0603; AGILE_PN: 370-75076; CAD_APPROVED: Yes; HEIGHT: 0.8MM; MFG_NAME01: LITE ON; MFG_PN01: LTST-C190KSKT; ROHS: Yes; SILK: ASLEEP
D509 = LED_QUAD_GRN: LED GRN QUAD 25mA RA TH; AGILE_PN: 370-76782; CAD_APPROVED: Yes; HEIGHT: 12.25MM; MFG_NAME01: Kingbright; MFG_PN01: WP914CK/4GDT; ROHS: Yes; Temp_Range: -40 to +85C
J13 = CONN_HDR_2X1: HDR 1X2 TH 50MIL SP 165H AU 91L; AGILE_PN: 210-80212; CAD_APPROVED: Yes; HEIGHT: 4.2MM; MFG_NAME01: SULLINS ELECTRONICS CORP; MFG_PN01: GRPB021VWVN-RC; ROHS: Yes; SILK: TEST_SEL
J14 = CONN_HDR_2X1: HDR 1X2 TH 50MIL SP 165H AU 91L; AGILE_PN: 210-80212; CAD_APPROVED: Yes; HEIGHT: 4.2MM; MFG_NAME01: SULLINS ELECTRONICS CORP; MFG_PN01: GRPB021VWVN-RC; ROHS: Yes; SILK: RST_REQ_EN
J15 = CONN_HDR_5X2: HDR 2X5 SMT 50MIL CTR 246H AU; AGILE_PN: 211-79478; CAD_APPROVED: Yes; HEIGHT: 6.25MM; MFG_NAME01: SAMTEC; ROHS: Yes; SILK: CPU-JTAG
J58 = ZX62RD-AB-5P8_USB_MICROAB: CON 5 USB2.0 MICRO-B RA SMT 0.65MM; AGILE_PN: 211-80639; CAD_APPROVED: Yes; HEIGHT: 1.77MM; MFG_NAME01: MOLEX; MFG_PN01: 0476420001; ROHS: Yes; SILK: Micro USB_Console; Temp_Range: -30C to +85C
J60 = CONN_HDR_6X1: HDR 1X6 TH 100MIL SP 330H SN 100L; AGILE_PN: 210-80604; CAD_APPROVED: Yes; HEIGHT: 8.38MM; MFG_NAME01: SAMTEC; MFG_PN01: TSW-106-07-T-S; ROHS: Yes; SILK: (UART2 & UART4)
J72 = CONN_HDR_2X1: HDR 1X2 TH 50MIL SP 165H AU 91L; AGILE_PN: 210-80212; CAD_APPROVED: Yes; HEIGHT: 4.2MM; MFG_NAME01: SULLINS ELECTRONICS CORP; MFG_PN01: GRPB021VWVN-RC; ROHS: Yes; SILK: UART_SEL
J73 = HDR-1X4: HDR 1X4 TH 100MIL CTR  338H AU 100L; AGILE_PN: 210-81082; CAD_APPROVED: Yes; HEIGHT: 8.6MM; MFG_NAME01: SAMTEC; MFG_PN01: TSW-104-07-F-S; ROHS: Yes; SILK: (UART1)
Q4 = NMOSFET_3P_ESD_DIODE: TRAN NMOS SW 0.9V DRIVE 50V UMT3; AGILE_PN: 480-78966; CAD_APPROVED: Yes; HEIGHT: 0.9MM; MFG_NAME01: ROHM; ROHS: Yes
R161 R167-R170 R185 R187 R355 R819 R823 R840 R859-R862 R871 R872 R874 R875 R885 R944 = RES: RES MF 4.70K 1/16W 1% 0402; AGILE_PN: 470-75418; CAD_APPROVED: Yes; FPLIST: RC0402_25,RC0402_HD,0402_CC; HEIGHT: 0.4mm; MFG_NAME01: WALSIN TECHNOLOGY CORP.; MFG_PN01: WR04X4701FTL; ROHS: Yes; Tolerance: 1%
R172 R177 R824 = RES: RES MF 4.70K 1/16W 1% 0402; AGILE_PN: 470-75418; ASSY_OPT: DNP; CAD_APPROVED: Yes; FPLIST: RC0402_25,RC0402_HD,0402_CC; HEIGHT: 0.4mm; MFG_NAME01: WALSIN TECHNOLOGY CORP.; MFG_PN01: WR04X4701FTL; ROHS: Yes; Tolerance: 1%
R186 = RES: RES MF 10.0 OHM 1/16W 1% 0402; AGILE_PN: 470-76090; CAD_APPROVED: Yes; FPLIST: RC0402_25,RC0402_HD,0402_CC; HEIGHT: 0.4MM; MFG_NAME01: BOURNS; MFG_PN01: CR0402-FX-10R0GLF; ROHS: Yes; Tolerance: 1%
R191 R924 R925 R948 = RES: RES MF 330 OHM 1/16W 1% 0402; AGILE_PN: 470-80566; CAD_APPROVED: Yes; FPLIST: RC0402_25,RC0402_HD,0402_CC; HEIGHT: 0.4MM; MFG_NAME01: WALSIN TECHNOLOGY CORP.; MFG_PN01: WR04X3300FTL; ROHS: Yes; Tolerance: 1%
R298 R299 R302-R305 R825 R841 R843 R864-R868 = RES: RES MF 10K 1/5W 1% AEC-Q200 0402; AGILE_PN: 470-80881; CAD_APPROVED: Yes; FPLIST: RC0402_25,RC0402_HD,0402_CC; HEIGHT: 0.4MM; MFG_NAME01: VISHAY INTERTECHNOLOGY; MFG_PN01: CRCW040210K0FKEDHP; ROHS: Yes; Temp_Range: -55&#8451; to 155&#8451;; Tolerance: 1%
R849 = RES: RES MF 22.1K 1/10W 1% AEC-Q200 0402; AGILE_PN: 470-30984; CAD_APPROVED: Yes; FPLIST: RC0402_25,RC0402_HD,0402_CC; HEIGHT: 0.40 MM; MFG_NAME01: KOA SPEER; MFG_PN01: RK73H1ETTP2212F; ROHS: Yes; Temp_Range: -55C to +155C; Tolerance: 1%
R850 = RES: RES MF 47.5K 1/16W 1% 0402; AGILE_PN: 470-80836; CAD_APPROVED: Yes; FPLIST: RC0402_25,RC0402_HD,0402_CC; HEIGHT: 0.4MM; MFG_NAME01: WALSIN TECHNOLOGY CORP.; MFG_PN01: WR04X4752FTL; ROHS: Yes; Temp_Range: -55°C ~ 155°C; Tolerance: 1%
R863 = RES: RES MF 100 OHM 1/20W 1% AEC-Q200 0201; AGILE_PN: 470-81361; CAD_APPROVED: Yes; FPLIST: RC0201,0201_CC; HEIGHT: 0.26 MM; MFG_NAME01: YAGEO AMERICA; MFG_PN01: AC0201FR-07100RL; ROHS: Yes; Temp_Range: -55&#8451; to 155&#8451;
R920 = RES: RES MF ZERO OHM 1/10W -- 0402; AGILE_PN: 470-79965; ASSY_OPT: DNP; CAD_APPROVED: Yes; FPLIST: RC0402_25,RC0402_HD,RC0402_X2,0402_CC; HEIGHT: 0.4MM; MFG_NAME01: Panasonic; MFG_PN01: ERJ-2GE0R00X; ROHS: Yes
TP126 TP142 = TestLoop: TEST POINT PAD 0.5MM DIA SMT, NO PART TO ORDER; AGILE_PN: 211-77484; CAD_APPROVED: Yes; HEIGHT: 0.1MM; ROHS: Yes
U536 = CP2102N_QFN20: IC USB-TO-UART BRIDGE 3-3.6V QFN20; AGILE_PN: 312-82164; CAD_APPROVED: Yes; HEIGHT: 0.8MM; MFG_NAME01: SILICON LABORATORIES; MFG_PN01: CP2102N-A01-GQFN20; ROHS: Yes; Temp_Range: -40 to +85C
U554 = NX3DV42GU_XQFN_10P_A: IC LIN SW DPDT DUAL USB 2.0 3-4.3V XQFN10; AGILE_PN: 312-81289; CAD_APPROVED: Yes; HEIGHT: 0.5MM; MFG_NAME01: NXP SEMICONDUCTORS; MFG_PN01: NX3DV42GU,115; ROHS: Yes
U543-U545 U563 U564 = PUSB3AB6: DIODE ARRAY ESD PROTECTION 15 kV 3.3V XSON7; AGILE_PN: 480-78930; ASSY_OPT: DNP; CAD_APPROVED: Yes; HEIGHT: 0.5MM; MFG_NAME01: NEXPERIA; MFG_PN01: PUSB3AB6Z; ROHS: Yes
J67 = CONN_HDR_10X2: HDR 2X10 SMT 100MIL CTR 380H AU; AGILE_PN: 211-30042; CAD_APPROVED: Yes; HEIGHT: 9.85mm; MFG_NAME01: SAMTEC; MFG_PN01: TSM-110-01-L-DV-M-TR; ROHS: Yes
R301 R558 R940 = RES: RES MF 4.7K 1/10W 1% AEC-Q200 0402; AGILE_PN: 470-81976; CAD_APPROVED: Yes; FPLIST: RC0402_25,RC0402_HD,0402_CC; HEIGHT: 0.4MM; MFG_NAME01: KOA SPEER; MFG_PN01: RK73H1ETTP4701F; ROHS: Yes; Temp_Range: -55C to +155C; Tolerance: 1%
R870 = RES: RES MF 10 OHM 1/16W 1% AEC-Q200 0402; AGILE_PN: 470-80978; CAD_APPROVED: Yes; FPLIST: RC0402_25,RC0402_HD,0402_CC; HEIGHT: 0.4MM; MFG_NAME01: KOA SPEER; MFG_PN01: RK73H1ETTP10R0F; ROHS: Yes; Tolerance: 1%
SW6 = SW2P_SPST: SW SPST MOM NO TACT 20MA 12V SMT; AGILE_PN: 510-78069; CAD_APPROVED: Yes; HEIGHT: 2.3MM; MFG_NAME01: Fodot Electronics Co.,Ltd.; MFG_PN01: T044S-N020FRT30B; ROHS: Yes
U54 = ADM8611_WLCSP_6P: IC SUPERVISORY ULTRALOW PWR 0.9-5.5V WLCSP6; AGILE_PN: 315-81882; CAD_APPROVED: Yes; HEIGHT: 0.66MM; MFG_NAME01: ANALOG DEVICES; ROHS: Yes; Temp_Range: -40C to +85C
U55 = 74AUP1G11GW: IC GATE AND 3INPUT 0.8-3.6V SOT363; AGILE_PN: 312-81800; CAD_APPROVED: Yes; HEIGHT: 1.1MM; MFG_NAME01: NEXPERIA; MFG_PN01: 74AUP1G11GW,125; ROHS: Yes; Temp_Range: -40C to +125C
U56 U114 U533 = 74AUP1G07GW: IC BUF NON-INV SGL 1.65-5.5V TSSOP5; AGILE_PN: 312-81328; CAD_APPROVED: Yes; HEIGHT: 1.1 MM; MFG_NAME01: NEXPERIA; MFG_PN01: 74LVC1G07GW,125; ROHS: Yes
U58 U60 U62 U534 U546 U547 U562 = GATE_AND_SGL: IC GATE AND 2 INPUT OPEN DRAIN OUTPUT 0.8-3.6V TSSOP5; AGILE_PN: 312-80643; CAD_APPROVED: Yes; HEIGHT: 1.1 MM; MFG_NAME01: NEXPERIA; MFG_PN01: 74AUP1G09GW,125; ROHS: Yes
U35-U37 U539 U540 U555 = 74LVC2T45DC_8P: IC TRANSLATING XCVR DUAL BIT/SUPPLY TS 1.2-5.5V VSSOP8; AGILE_PN: 312-81751; CAD_APPROVED: Yes; HEIGHT: 1MM; MFG_NAME01: NEXPERIA; ROHS: Yes; Temp_Range: -40°C to +125°C
J55 = CON8_SDCARD_DETECT: CON 8 SKT SD/MMC RA SMT 43MIL SP 84H AU; AGILE_PN: 211-80169; CAD_APPROVED: Yes; HEIGHT: 2.13MM; MFG_NAME01: ANYTRONIC CORPORATION LIMITED; ROHS: Yes; SILK: MICRO SD SLOT; Temp_Range: -25C to +85C
J56 J57 = CONN_HDR_8X1: CON 1X8 SKT TH 100MIL SP 344H AU 394L; AGILE_PN: 210-81601; CAD_APPROVED: Yes; HEIGHT: 8.75MM; MFG_NAME01: ANYTRONIC CORPORATION LIMITED; MFG_PN01: 08001S3 0811-100-29LF; ROHS: Yes; Temp_Range: -40°C to +105°C
J66 = CONN_HDR_8X1: HDR 1X8 TH 100MIL SP 330H AU 100L; AGILE_PN: 210-75691; CAD_APPROVED: Yes; HEIGHT: 8.382 MM; MFG_NAME01: SAMTEC; MFG_PN01: TSW-108-07-G-S; ROHS: Yes
R239 = RES: RES MF 33 OHM 1/16W 5% 0402; AGILE_PN: 470-75634; CAD_APPROVED: Yes; FPLIST: RC0402_25,RC0402_HD,0402_CC; HEIGHT: 0.41mm; MFG_NAME01: SMEC; MFG_PN01: RC73L2Z330JTF; ROHS: Yes; Tolerance: 5%
TVS1 = DIODE_TVS_BIDIR: DIODE TVS BIDIR 2A 0.10pF 9.8V AEC-Q101 0402; AGILE_PN: 480-78761; ASSY_OPT: DNP; CAD_APPROVED: Yes; HEIGHT: 0.43MM; MFG_NAME01: TE Connectivity Ltd; MFG_PN01: SESD0402X1BN-0010-098; ROHS: Yes
U14 = LS1043_1046_SS: IC MCU LS1046 and LS1043 FBGA780; AGILE_PN: TMP-WF-33894; CAD_APPROVED: Yes; HEIGHT: 2.61/2.07MM; MFG_NAME01: NXP SEMICONDUCTORS; PRE_APN: 344-02328; ROHS: Yes
U38 U39 = PUSB3AB6: DIODE ARRAY ESD PROTECTION 15 kV 3.3V XSON7; AGILE_PN: 480-78930; CAD_APPROVED: Yes; HEIGHT: 0.5MM; MFG_NAME01: NEXPERIA; MFG_PN01: PUSB3AB6Z; ROHS: Yes
U548 = NTB0102_8P: IC XCVR 2-BIT 3-STATE 1.2-3.6V/1.65-5.5V XSON8; AGILE_PN: 312-80757; CAD_APPROVED: Yes; HEIGHT: 0.5MM; MFG_NAME01: NXP SEMICONDUCTORS; MFG_PN01: NTB0102GT,115; ROHS: Yes

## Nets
2V5: R871.2 R872.2 ; also on sheet 6 8 10 11 15
3V3: C278.1 C450.1 C452.1 C454.1 C488.1 C1298.1 C1299.1 C1302.1 C1304.1 C1307.1 C1309.1 C1310.1 C1313.1 C1315.1 C1316.1 C1327.1 C1464.1 C1465.1 C1466.1 C1555.1 D2.A(ANODE) D509.2(ANODE_1) D509.4(ANODE_2) D509.6(ANODE_3) J55.4(VDD) J56.7 J66.1 J73.1 R245.1 R828.1 R829.1 R830.1 R831.1 R832.1 R833.1 R834.1 R840.2 R843.1 R864.1 R869.1 R878.1 R920.1 R940.1 R944.1 TVS1.1(A1) U35.1(VCCA) U36.1(VCCA) U37.8(VCCB) U54.A1(VCC) U530.5(VCC) U535.5(VCC) U536.6(VDD) U536.7(VREGIN) U539.1(VCCA) U540.1(VCCA) U547.5(VCC) U548.7(VCCB) U551.5(VCC) U554.9(VCC) U555.1(VCCA) U562.5(VCC) ; also on sheet 5 6 7 8 9 13 14 16
5V0: C457.1 C1320.1 C1329.1 J57.7 U40.B1(VINT1) U40.B2(VINT2) U40.C1(VINT3) U550.B1(VINT1) U550.B2(VINT2) U550.C1(VINT3) ; also on sheet 5
GND: C278.2 C449.2 C450.2 C451.2 C452.2 C453.2 C454.2 C457.2 C458.2 C459.2 C460.2 C487.2 C488.2 C489.2 C492.2 C493.2 C497.2 C498.2 C905.2 C1280.2 C1297.2 C1298.2 C1299.2 C1302.2 C1304.2 C1306.2 C1307.2 C1308.2 C1309.2 C1310.2 C1313.2 C1314.2 C1315.2 C1316.2 C1317.2 C1320.2 C1321.2 C1322.2 C1323.2 C1324.2 C1327.2 C1328.2 C1329.2 C1460.2 C1461.2 C1462.2 C1463.2 C1464.2 C1465.2 C1466.2 C1467.2 C1555.2 D4.C(CATHODE) D508.C(CATHODE) J13.1 J15.3(A2) J15.5(A3) J55.6(VSS) J56.8 J57.8 J58.5(P5) J60.1 J66.5 J67.7 J67.8 J67.13 J67.14 J70.4(GND1) J70.7(GND_DRAIN1) J70.13(GND2) J70.16(GND_DRAIN2) J73.4 L11.2 L514.2 Q4.1(SOURCE) R177.2 R185.2 R188.1 R192.2 R241.2 R242.2 R243.2 R248.2 R249.2 R257.2 R473.2 R474.2 R793.2 R823.2 R841.1 R850.2 R874.2 R875.2 R880.2 R881.2 R882.2 R883.2 R885.2 R916.2 R917.2 R921.2 SW6.1(SW1) TVS1.2(A2) U14.A3(USB3_RX_P) U14.A4(USB3_RX_M) U14.AD21(FA_ANALOG_PIN) U14.AG21(FA_ANALOG_G_V) U35.4(GND) U35.5(DIR) U36.4(GND) U36.5(DIR) U37.4(GND) U37.5(DIR) U37.6(2B) U38.2(GND) U39.2(GND) U40.B3(GND1) U40.C3(GND2) U40.D3(GND3) U42.1(GND) U44.3(GND1) U44.8(GND2) U54.A2(GND1) U54.B2(GND2) U55.2(GND) U56.3(GND) U58.3(GND) U60.3(GND) U62.3(GND) U114.3(GND) U530.3(GND) U533.3(GND) U534.3(GND) U535.3(GND) U536.3(GND_1) U536.12(GND_2) U536.21(EPAD) U537.1(GND) U539.4(GND) U539.5(DIR) U540.4(GND) U540.5(DIR) U543.2(GND) U544.2(GND) U545.2(GND) U546.3(GND) U547.3(GND) U548.2(GND) U550.B3(GND1) U550.C3(GND2) U550.D3(GND3) U551.3(GND) U552.1(GND) U553.3(GND1) U553.8(GND2) U554.3(GND) U554.8(~{OE}) U555.4(GND) U555.5(DIR) U555.6(2B) U562.3(GND) U563.2(GND) U564.2(GND) ; also on sheet 5 6 7 8 9 10 11 12 13 14 15 16
GND_EARTH: C1460.1 C1461.1 C1462.1 C1463.1 C1467.1 J55.SH1(GND1) J55.SH2(GND2) J55.SH3(GND3) J55.SH4(GND4) J58.S1(SHLD1) J58.S2(SHLD2) J58.S3(SHLD3) J58.S4(SHLD4) J70.S1(G1) J70.S2(G2) J70.S3(G3) J70.S4(G4) R916.1 R917.1 R921.1 ; also on sheet 5 15
VBUS: R849.1 R850.1 U536.8(VBUS)
VCC_USB1_PWR: C458.1 C459.1 C460.1 L11.1 U14.E7(USB1_VBUS) U40.C2(VBUS1) U40.D1(VBUS2) U40.D2(VBUS3)
VCC_USB2_PWR: C1321.1 C1322.1 C1323.1 L514.1 R255.1 R471.2 U550.C2(VBUS1) U550.D1(VBUS2) U550.D2(VBUS3)
VDD_LP: R560.2 ; also on sheet 8 16
C_USB1_TX_N: C463.1 J70.8(SSTX1-) U553.1(CH1) U553.10(NC4)
C_USB1_TX_P: C464.1 J70.9(SSTX1+) U553.2(CH2) U553.9(NC3)
C_USB2_TX_N: C1326.2 J70.17(SSTX2-) U553.5(CH4) U553.6(NC1)
C_USB2_TX_P: C1325.2 J70.18(SSTX2+) U553.4(CH3) U553.7(NC2)
CLK_RTC: U14.F17(RTC) ; also on sheet 16
CONN_SPI_CLK: J66.4 U539.2(1A)
CONN_SPI_CS1_B: J66.6 U36.2(1A)
CONN_SPI_CS2_B: J66.7 U540.2(1A)
CONN_SPI_CS3_B: J66.8 U540.3(2A)
CONN_SPI_MISO: J66.3 R941.2
CONN_SPI_MOSI: J66.2 U35.2(1A)
CP2102_SIN: J72.2 U536.18(TXD)
CP2102_SOUT: R837.2 R841.2 U536.17(RXD)
CPU_ASLEEP: Q4.2(GATE) R192.1 U14.E9(ASLEEP)
CPU_CKSTP_OUT_B: R187.1 U14.G15(CKSTP_OUT_B)
CPU_CLKOUT: TP126.1(Pin1) U14.G16(CLK_OUT)
CPU_EVT0_B: R167.2 U14.E10(EVT0_B)
CPU_EVT1_B: R168.2 U14.E13(EVT1_B)
CPU_EVT2_B: R169.2 U14.E8(EVT2_B)
CPU_EVT3_B: R170.2 U14.E12(EVT3_B)
CPU_EVT4_B: R161.2 U14.E11(EVT4_B)
CPU_HRESET_B: R825.2 U14.F8(HRESET_B) U114.2(A) U533.4(Y)
CPU_ID: R819.1 U14.AG3(EC2_TX_EN) ; also on sheet 8
CPU_JTAG_BSR_VSEL: R172.2 R185.1 U14.J19(JTAG_BSR_VSEL)
CPU_JTAG_RST_B: J15.10(B5) R303.2 U55.1(A)
CPU_JTAG_VTREF: J15.1(A1) R186.2
CPU_PORESET_B: TP142.1(Pin1) U14.F9(PORESET_B) U55.4(Y)
CPU_RESET_REQ_B: J14.2 U14.F10(RESET_REQ_B)
CPU_SPI_PCS0: R861.2 U14.U1(SPI_PCS0) U36.6(2B)
CPU_SPI_PCS1: R862.2 U14.R3(SPI_PCS1) U36.7(1B)
CPU_SPI_PCS2: R860.2 U14.T3(SPI_PCS2) U540.7(1B)
CPU_SPI_PCS3: R859.2 U14.V1(SPI_PCS3) U540.6(2B)
CPU_SPI_SCK: U14.U2(SPI_SCK) U539.6(2B) U539.7(1B)
CPU_SPI_SIN: U14.U3(SPI_SIN) U37.2(1A)
CPU_SPI_SOUT: U14.V3(SPI_SOUT) U35.6(2B) U35.7(1B)
CPU_TBSCAN_EN_B: R171.2 R177.1 U14.F19(TBSCAN_EN_B)
CPU_TCK: J15.4(B2) R355.2 U14.E18(TCK)
CPU_TDI: J15.8(B4) U14.G17(TDI)
CPU_TDO: J15.6(B3) U14.E20(TDO)
CPU_TMS: J15.2(B1) U14.G18(TMS)
CPU_TRST_B: R305.2 U14.E19(TRST_B) U56.4(Y)
DDR_CLK_100MHZ_LVCMOS : U14.J20(DDRCLK) ; also on sheet 13
DIFF_SYSCLK_N: R863.2 U14.AB13(DIFF_SYSCLK_B) ; also on sheet 13
DIFF_SYSCLK_P: R863.1 U14.AA13(DIFF_SYSCLK) ; also on sheet 13
EMI2_MDC: R870.2 R872.1 ; also on sheet 15
EMI2_MDIO: R871.1 U14.AH3(EMI2_MDIO) ; also on sheet 15
FTM7_CH0: U548.5(A1) ; also on sheet 12
FUSE_PWR_STATUS#: R948.2 ; also on sheet 9
GPIO3_02: J67.6 U14.Y3(EC1_TXD3) U543.4(CH3)
GPIO3_03: J67.10 U14.Y4(EC1_TXD2) U544.1(CH1)
GPIO3_04: J67.4 U14.AA3(EC1_TXD1) U543.3(CH2)
GPIO3_05: J67.5 U14.AB3(EC1_TXD0) U543.5(CH4)
GPIO3_06: J67.2 U14.AB4(EC1_TX_EN) U543.1(CH1)
GPIO3_07: J67.12 U14.W4(EC1_GTX_CLK) U544.3(CH2)
GPIO3_08: J67.9 U14.AC3(EC1_GTX_CLK125) U544.7(CH6)
GPIO3_09: J67.20 U14.W2(EC1_RXD3) U545.4(CH3)
GPIO3_10: J67.16 U14.Y1(EC1_RXD2) U545.1(CH1)
GPIO3_11: J67.1 U14.AA1(EC1_RXD1) U543.7(CH6)
GPIO3_12: J67.3 U14.AA2(EC1_RXD0) U543.6(CH5)
GPIO3_13: J67.18 U14.W1(EC1_RX_CLK) U545.3(CH2)
GPIO3_14: J67.11 U14.AB1(EC1_RX_DV) U544.6(CH5)
GPIO3_15: J67.15 U14.AD3(EC2_TXD3) U545.7(CH6)
GPIO3_16: J67.17 U14.AE3(EC2_TXD2) U545.6(CH5)
GPIO3_17: J67.19 U14.AE4(EC2_TXD1) U545.5(CH4)
GPIO3_21: U14.AG4(EC2_GTX_CLK125) U548.4(A2)
GPIO_FUSE_PROG: U14.AE1(EC2_RXD1) ; also on sheet 9
GVDD: R558.1 ; also on sheet 6 9 10 11
I2C1_SCL: U14.N1(IIC1_SCL) ; also on sheet 16
I2C1_SDA: U14.M1(IIC1_SDA) ; also on sheet 16
I2C1_uBUS_SCL: J57.5 ; also on sheet 16
I2C1_uBUS_SDA: J57.6 ; also on sheet 16
I2C3_SCL: U554.4(HSD1-) ; also on sheet 16
I2C3_SDA: U554.5(HSD1+) ; also on sheet 16
I2C3_USB2_SEL: U554.10(S) U555.2(1A)
I2C3_USB2_SEL_IO: R885.1 U14.AD1(EC2_RXD2) U555.7(1B)
I2C4_SCL: U14.M3(IIC4_SCL) ; also on sheet 16
I2C4_SDA: U14.N3(IIC4_SDA) ; also on sheet 16
IRQ_RTC_B: U14.J5(IRQ05) ; also on sheet 16
LED_ASLEEP: D2.C(CATHODE) R191.2
LP_TMP_DETECT_B: R560.1 U14.H12(TA_BB_TMP_DETECT_B)
MR_B: R302.2 U54.C1(~{MR}) U534.4(Y)
OVDD: C449.1 C451.1 C453.1 C487.1 C489.1 C492.1 C493.1 C497.1 C498.1 C905.1 C1297.1 C1306.1 C1308.1 C1314.1 C1317.1 C1328.1 R157.1 R158.2 R160.1 R161.1 R167.1 R168.1 R169.1 R170.1 R171.1 R172.1 R186.1 R187.2 R298.1 R299.1 R301.1 R302.1 R303.1 R304.1 R305.1 R355.1 R819.2 R824.2 R825.1 R859.1 R860.1 R861.1 R862.1 R865.1 R866.1 R867.1 R868.1 U35.8(VCCB) U36.8(VCCB) U37.1(VCCA) U55.5(VCC) U56.5(VCC) U58.5(VCC) U60.5(VCC) U62.5(VCC) U114.5(VCC) U533.5(VCC) U534.5(VCC) U539.8(VCCB) U540.8(VCCB) U546.5(VCC) U548.3(VCCA) U548.6(OE) U555.8(VCCB) ; also on sheet 6 9 12 13 15 16
PMIC_INT_B: U14.K5(IRQ06) ; also on sheet 6
PORESET_B: R301.2 U54.C2(~{RESET}) U55.3(B) U56.2(A) U58.2(A) U60.2(A) U62.2(A) U533.2(A) U546.2(A) ; also on sheet 12 16
PS_V5V0_PG: U562.1(B) ; also on sheet 5
PS_VDD_PG: U562.2(A) ; also on sheet 7
QSGPHY1_INT_B: U14.F15(IRQ01) ; also on sheet 15
QSGPHY1_RST_B: U62.4(Y) ; also on sheet 15
R_LED_ASLEEP: Q4.3(DRAIN) R191.1
R_USB1_LED: D4.A(ANODE) R244.2
R_USB2_LED: D508.A(ANODE) R879.2
RESET_MCU_B: U547.2(A) ; also on sheet 6
RESET_REQ_B: J14.1 R298.2 U534.2(A)
RST_MEM_B: R558.2 U114.4(Y) ; also on sheet 10 11
RSV_IO: R823.1 R824.1 U14.AF3(EC2_TXD0)
SCAN_MODE: R160.2 U14.H19(SCAN_MODE_B)
SD_CLK: J55.5(CLK) R239.2 R832.2 U39.1(CH1)
SD_CMD: J55.3(CMD) R833.2 U14.P2(SDHC_CMD) U38.4(CH3)
SD_DATA0: J55.7(DAT0) R828.2 U14.P1(SDHC_DAT0) U38.7(CH6)
SD_DATA1: J55.8(DAT1) R829.2 U14.R2(SDHC_DAT1) U38.1(CH1)
SD_DATA2: J55.1(DAT2) R830.2 U14.R1(SDHC_DAT2) U39.4(CH3)
SD_DATA3: J55.2(CD/DAT3) R831.2 U14.T1(SDHC_DAT3) U39.5(CH4)
SDHC_CD_B: J55.9(DETECT) R834.2 U14.K3(IIC2_SCL) U38.5(CH4)
SDHC_WP: R241.1 U14.L3(IIC2_SDA)
SLOT1_RST_B: U58.4(Y) ; also on sheet 14
SLOT2_RST_B: U60.4(Y) ; also on sheet 14
SOC_SD_CLK: R239.1 U14.P3(SDHC_CLK)
SPI_MISO: R941.1 R942.1 U37.7(1B)
SW_QSGPHY1_RST_B: R867.2 U14.AF1(EC2_RX_DV) U62.1(B)
SW_RST: R299.2 SW6.2(SW2) U534.1(B)
SW_SLOT1_RST_B: R865.2 U14.AC4(EC2_GTX_CLK) U58.1(B)
SW_SLOT2_RST_B: R866.2 U14.AC1(EC2_RX_CLK) U60.1(B)
SW_uBUS1_RST: R868.2 U14.AE2(EC2_RXD0) U546.1(B)
SYS_CLK_100MHz_LVCMOS: U14.G14(SYSCLK) ; also on sheet 13
SYS_PGOOD#: R924.2 U535.4(Y)
SYS_STATUS_LT#: R925.2 ; also on sheet 9
TDI_ANODE: U14.J13(TD1_ANODE) ; also on sheet 16
TDI_CATHODE: U14.H13(TD1_CATHODE) ; also on sheet 16
TEST_SEL_B: J13.2 R157.2 U14.F20(TEST_SEL_B)
THERM_FAULT_B: U14.J4(IRQ04) ; also on sheet 16
THERM_WARN_B: U14.J3(IRQ03) ; also on sheet 16
TMP_DETECT_B: R158.1 U14.H20(TA_TMP_DETECT_B)
UART1_SIN: J72.1 J73.3 U14.H2(UART1_SIN) U563.4(CH3)
UART1_SOUT: J73.2 R837.1 U14.H1(UART1_SOUT) U563.1(CH1)
UART2_CTS_B: J60.6 U14.M2(UART2_CTS_B) U564.6(CH5)
UART2_RTS_B: J60.2 U14.L1(UART2_RTS_B) U564.5(CH4)
UART2_SIN: J60.4 U14.K1(UART2_SIN) U564.1(CH1)
UART2_SOUT: J60.5 U14.L2(UART2_SOUT) U564.4(CH3)
UART_PWR2: J60.3 R920.2
uBUS1_AN: R401.1 U548.8(B1)
uBUS1_INT: J57.2 R869.2 U14.L5(IRQ07)
uBUS1_PWM: J57.1 U548.1(B2)
uBUS1_RST: J56.2 R864.2 U546.4(Y)
uBUS1_SPI_CLK: J56.4 U539.3(2A)
uBUS1_SPI_CS0_B: J56.3 U36.3(2A)
uBUS1_SPI_MISO: J56.5 R942.2
uBUS1_SPI_MOSI: J56.6 U35.3(2A)
uBUS1_UART_SIN: J57.3 U14.J1(UART1_CTS_B)
uBUS1_UART_SOUT: J57.4 U14.J2(UART1_RTS_B)
USB1_DRVVBUS: R242.1 U14.H6(USB_DRVVBUS) U40.A1(EN)
USB1_ID: R248.1 U14.F5(USB1_ID)
USB1_ILIM: R243.1 U40.A3(ILIM)
USB1_ISO_VOUT: C1280.1 J70.1(VBUS1) L11.3 R244.1 U42.4(VCC)
USB1_PWRFAULT: R793.1 U14.G6(USB_PWRFAULT) U530.4(Y)
USB1_RESREF: R249.1 U14.G3(USB1_RESREF)
USB1_RX_N: J70.5(SSRX1-) U14.E4(USB1_RX_M) U44.4(CH3) U44.7(NC2)
USB1_RX_P: J70.6(SSRX1+) U14.E3(USB1_RX_P) U44.5(CH4) U44.6(NC1)
USB1_TX_N: C463.2 U14.F2(USB1_TX_M)
USB1_TX_P: C464.2 U14.F1(USB1_TX_P)
USB1_UDM: J70.2(D1-) U14.E6(USB1_D_M) U42.3(IO2)
USB1_UDP: J70.3(D1+) U14.F6(USB1_D_P) U42.2(IO1)
USB2_DRVVBUS: R882.1 U550.A1(EN) U554.6(HSD2-)
USB2_DRVVBUS_I2C3_SCL: U14.L4(IIC3_SCL) U554.2(D-)
USB2_ID: R883.1 U14.D5(USB2_ID)
USB2_ILIM: R881.1 U550.A3(ILIM)
USB2_ISO_VOUT: C1324.1 J70.10(VBUS2) L514.3 R879.1 U552.4(VCC)
USB2_PWRFAULT: R880.1 U551.4(Y) U554.7(HSD2+)
USB2_PWRFAULT_I2C3_SDA: U14.M4(IIC3_SDA) U554.1(D+)
USB2_RESREF: R257.1 U14.G4(USB2_RESREF)
USB2_RX_N: J70.14(SSRX2-) U14.C4(USB2_RX_M) U44.2(CH2) U44.9(NC3)
USB2_RX_P: J70.15(SSRX2+) U14.C3(USB2_RX_P) U44.1(CH1) U44.10(NC4)
USB2_TX_N: C1326.1 U14.D2(USB2_TX_M)
USB2_TX_P: C1325.1 U14.D1(USB2_TX_P)
USB2_UDM: J70.11(D2-) U14.C6(USB2_D_M) U552.3(IO2)
USB2_UDP: J70.12(D2+) U14.D6(USB2_D_P) U552.2(IO1)
USB2_VBUS: R255.2 U14.C7(USB2_VBUS)
USB3_ID: R473.1 U14.B5(USB3_ID)
USB3_RESREF: R474.1 U14.G5(USB3_RESREF)
USB3_VBUS: R471.1 U14.A7(USB3_VBUS)
USB_CONN_DM: J58.2(P2) U536.5(D-) U537.3(IO2)
USB_CONN_DP: J58.3(P3) U536.4(D+) U537.2(IO1)
USB_CONN_PWR: J58.1(P1) R849.2 U537.4(VCC)
N18041442: R304.2 U55.6(C) U535.2(A) U547.4(Y)
N26524532: R245.2 U40.A2(~{FAULT}) U530.2(A)
N26874475: J15.9(A5) R188.2
N26911462: J56.1 R401.2
N26987601: R870.1 U14.AH4(EMI2_MDC)
N27008437: R874.1 U14.AG2(EMI1_MDC)
N27008440: R875.1 U14.AF2(EMI1_MDIO)
N27027375: R878.2 U550.A2(~{FAULT}) U551.2(A)
N27259526: D509.1(CATHODE) R924.1
N27259549: D509.3(CATHODE_2) R925.1
N27260803: R940.2 U547.1(B) U562.4(Y)
N28144784: R944.2 U536.9(~{RST})
N28148907: R840.1 U536.13(WAKEUP)
N28150385: R843.2 U536.15(CTS)
N28245014: D509.5(CATHODE_3) R948.1

Not connected (* = marked no-connect by the designer): D509 7(CATHODE_4) 8(ANODE_4); J15 7(A4)*; J58 4(P4)*; U14 A6(USB3_D_M) AC2(EC2_RXD3) B1(USB3_TX_P)* B2(USB3_TX_M)* B6(USB3_D_P) F11(IRQ00)* G7(EVT9_B)* H7(IRQ02)* M5(IRQ08)* N5(IRQ09)* P4(IRQ10)* W3(IRQ11)*; U37 3(2A); U38 3(CH2)* 6(CH5)*; U39 3(CH2)* 6(CH5)* 7(CH6); U54 B1(DNC)*; U56 1(NC)*; U114 1(NC)*; U530 1(NC)*; U533 1(NC)*; U535 1(NC)*; U536 1(GPIO1/RS485)* 2(GPIO0/CLK)* 10(NC)* 11(~{SUSPEND})* 14(SUSPEND)* 16(RTS) 19(GPIO3/RXT)* 20(GPIO2/TXT)*; U544 4(CH3) 5(CH4); U551 1(NC)*; U555 3(2A); U563 3(CH2)* 5(CH4) 6(CH5)* 7(CH6); U564 3(CH2)* 7(CH6)

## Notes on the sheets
sheet 17
- [SDHC_CD_B]
- [SDHC_WP]
- cfg_test_port_mux_sel
- [UART3_SIN]
- [UART3_SOUT]
- cfg_soc_use
- STATUS LEDS
- GPIO3_23=================>
  I2C3_USB2_SEL=0  for I2C3 on header  -> Default
  I2C3_USB2_SEL=1 for USB2_DRVVBUS/PWRFAULT
- UART Expansion Header
- USB-UART INTERFACE
- WITHOUT FLOW CONTROL
- [UART4_SOUT]
- Self-Powered Mode
- [UART4_SIN]
- Mates with FTDI standard 3V3 cable
  FTDI TTL-232R-3V3
  Or Connect with RS232/RS485/RS422 Expansion card
sheet 18
- Place at top
- ALL EC1 & EC2 signals are used as GPIOs
- GPIO Expansion Header [1.8V IOs]
- GPIO3_20
- GPIO3_26
- GPIO3_27
- GPIO3_25
- GPIO3_24
- GPIO3_23
- GPIO3_19
- GPIO3_18
- UNUSED
- CPU_ID:
  1       CPU_LS1046
  0       CPU_LS1043
- ->
- ->
sheet 19
- ->
- ->
- ->
- ->
- SPI Expansion Header
- SPI INTERFACE CS Mapping
  CS0                        Mikro-Click Module
  CS[1:2]                   SPI Expansion Header
- ->
- ->
- ->
- ->
- ->
- ->
- ->
- ->
- ->
- ->
- ->
- ->
- ->
- ->
- ->
- ->
- ->
- Micro SD CARD
- EVDD-3.3V
- EVDD-3.3V
- EVDD-3.3V
- EVDD-3.3V
- EVDD-3.3V
- EVDD-3.3V
- MIKRO-CLICK CONNECTORS
- CS0
- ->
- [UART3_SIN]
- ->
- [UART3_SOUT]
sheet 20
- NX5P3090UK USB CURRENT LIMITS
  ============================
  R_ILIM = 17.4K
  IMAX: 49495 * 17.4^-0.948 :: 3.30 A
  ITYP: 52775 * 17.4^-0.979 :: 3.20 A
  IMIN: 57949 * 17.4^-1.042 :: 2.95 A
- USB1 = Host Mode
- NX5P3090UK USB CURRENT LIMITS
  ============================
  R_ILIM = 17.4K
  IMAX: 49495 * 17.4^-0.948 :: 3.30 A
  ITYP: 52775 * 17.4^-0.979 :: 3.20 A
  IMIN: 57949 * 17.4^-1.042 :: 2.95 A
- USB2 = Host Mode
